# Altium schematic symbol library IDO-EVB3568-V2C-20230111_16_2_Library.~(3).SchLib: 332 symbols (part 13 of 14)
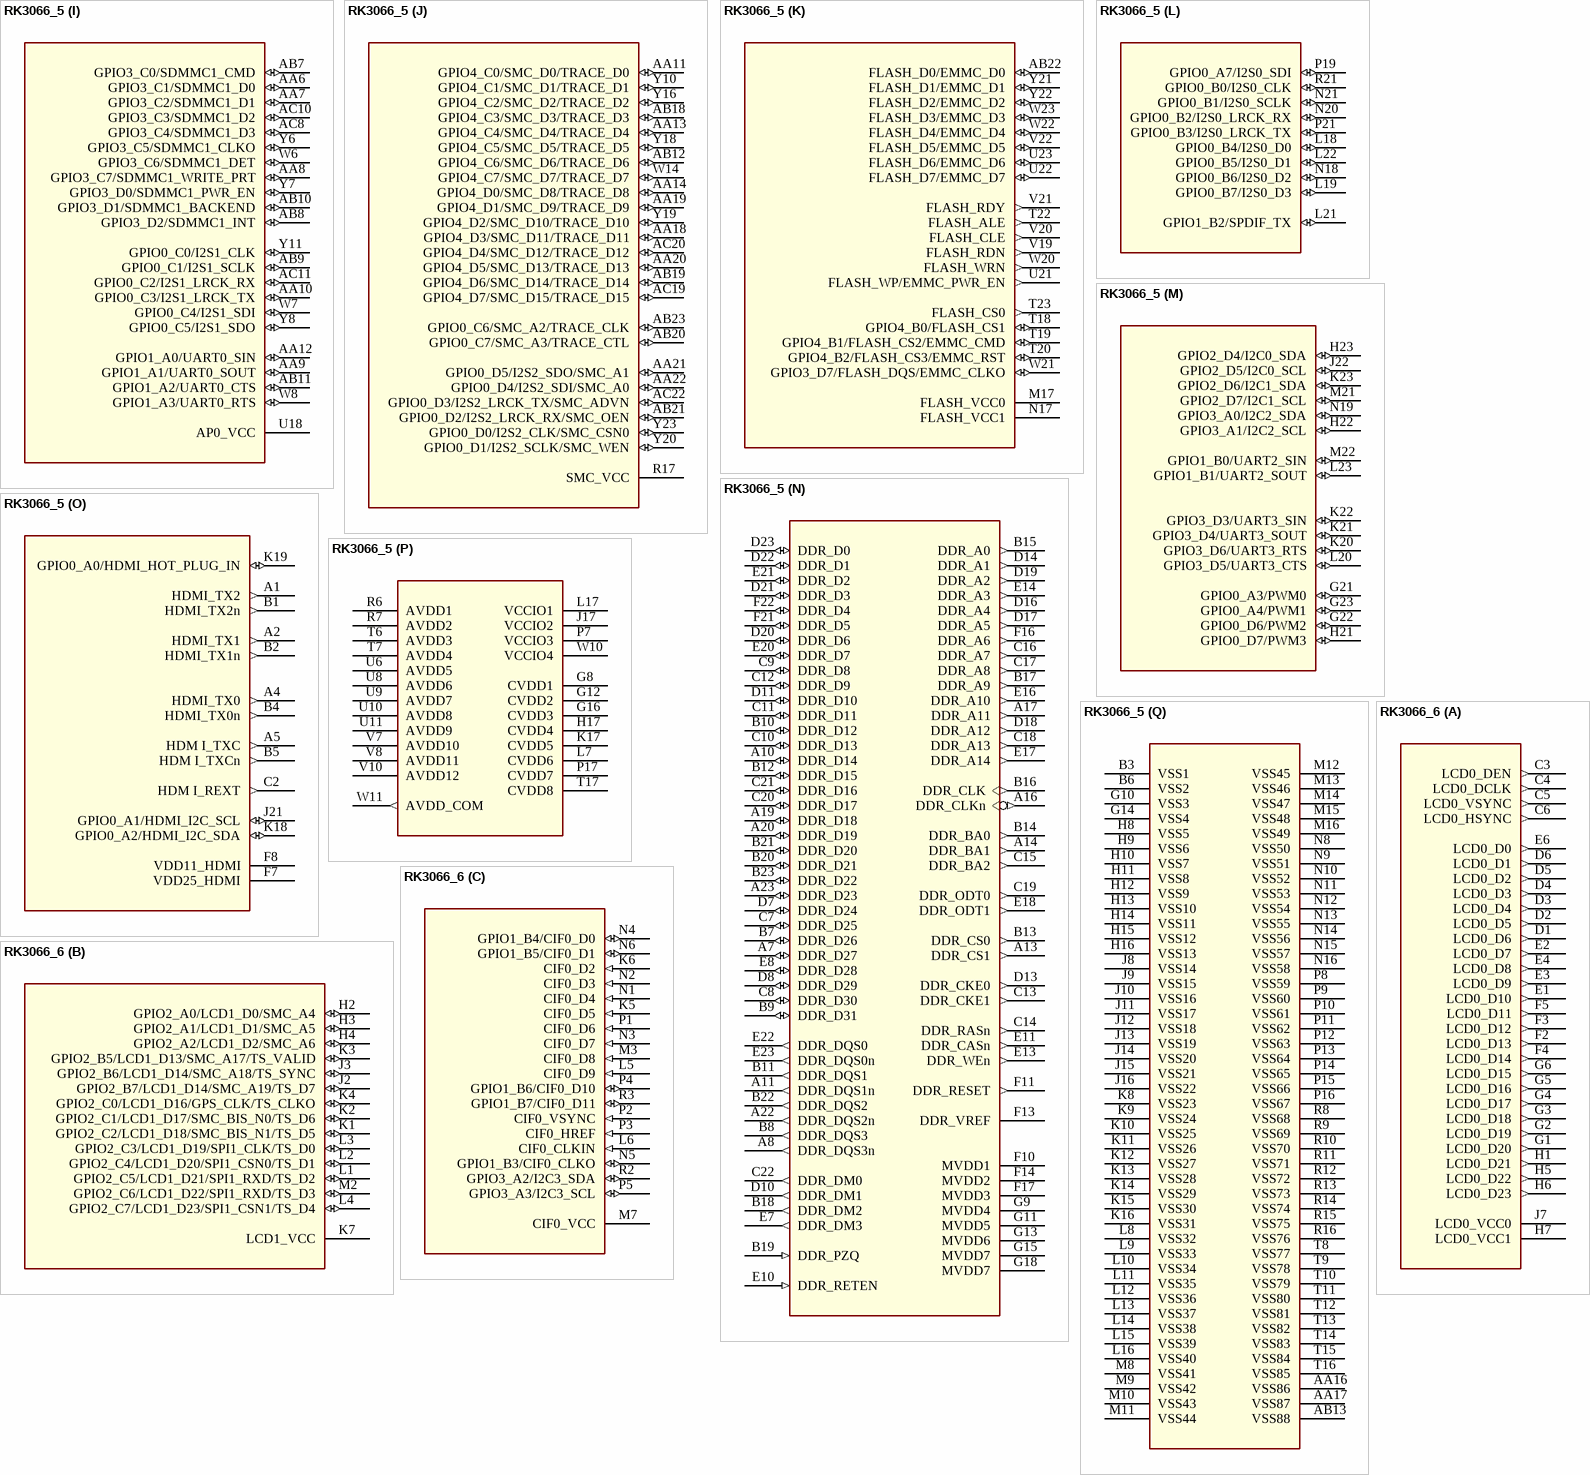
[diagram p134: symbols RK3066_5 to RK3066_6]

## RK3066_5
designator U?
Altium-Right: 230; Altium-Bottom: 180; Altium-Right1: 160; Altium-Bottom1: 120; Altium-Bottom2: 130; Altium-Bottom3: 280; Altium-Bottom4: 310; Altium-Bottom5: 270; Altium-Bottom6: 140; Altium-Bottom8: 530; Altium-Right9: 150; Altium-Bottom9: 250; Altium-Right10: 110; Altium-Bottom10: 170; Altium-Right11: 100; Altium-Bottom11: 470; Altium-Right12: 80; Altium-Bottom12: 350; Altium-Right13: 200; Altium-Bottom13: 190
footprint BGA453
part A pins: C3 LCD0_DEN (out), C4 LCD0_DCLK (out), C5 LCD0_VSYNC (out), C6 LCD0_HSYNC (out), D1 LCD0_D6 (out), D2 LCD0_D5 (out), D3 LCD0_D4 (out), D4 LCD0_D3 (out), D5 LCD0_D2 (out), D6 LCD0_D1 (out), E1 LCD0_D10 (out), E2 LCD0_D7 (out), E3 LCD0_D9 (out), E4 LCD0_D8 (out), E6 LCD0_D0 (out), F2 LCD0_D13 (out), F3 LCD0_D12 (out), F4 LCD0_D14 (out), F5 LCD0_D11 (out), G1 LCD0_D20 (out), G2 LCD0_D19 (out), G3 LCD0_D18 (out), G4 LCD0_D17 (out), G5 LCD0_D16 (out), G6 LCD0_D15 (out), H1 LCD0_D21 (out), H5 LCD0_D22 (out), H6 LCD0_D23 (out), H7 LCD0_VCC1 (power), J7 LCD0_VCC0 (power)
part B pins: H2 GPIO2_A0/LCD1_D0/SMC_A4 (io), H3 GPIO2_A1/LCD1_D1/SMC_A5 (io), H4 GPIO2_A2/LCD1_D2/SMC_A6 (io), J2 GPIO2_B7/LCD1_D14/SMC_A19/TS_D7 (io), J3 GPIO2_B6/LCD1_D14/SMC_A18/TS_SYNC (io), K1 GPIO2_C2/LCD1_D18/SMC_BIS_N1/TS_D5 (io), K2 GPIO2_C1/LCD1_D17/SMC_BIS_N0/TS_D6 (io), K3 GPIO2_B5/LCD1_D13/SMC_A17/TS_VALID (io), K4 GPIO2_C0/LCD1_D16/GPS_CLK/TS_CLKO (io), K7 LCD1_VCC (power), L1 GPIO2_C5/LCD1_D21/SPI1_RXD/TS_D2 (io), L2 GPIO2_C4/LCD1_D20/SPI1_CSN0/TS_D1 (io), L3 GPIO2_C3/LCD1_D19/SPI1_CLK/TS_D0 (io), L4 GPIO2_C7/LCD1_D23/SPI1_CSN1/TS_D4 (io), M2 GPIO2_C6/LCD1_D22/SPI1_RXD/TS_D3 (io)
part C pins: K5 CIF0_D5 (in), K6 CIF0_D2 (in), L5 CIF0_D9 (in), L6 CIF0_CLKIN (in), M3 CIF0_D8 (in), M7 CIF0_VCC (power), N1 CIF0_D4 (in), N2 CIF0_D3 (in), N3 CIF0_D7 (in), N4 GPIO1_B4/CIF0_D0 (io), N5 GPIO1_B3/CIF0_CLKO (io), N6 GPIO1_B5/CIF0_D1 (io), P1 CIF0_D6 (in), P2 CIF0_VSYNC (in), P3 CIF0_HREF (in), P4 GPIO1_B6/CIF0_D10 (io), P5 GPIO3_A3/I2C3_SCL (io), R2 GPIO3_A2/I2C3_SDA (io), R3 GPIO1_B7/CIF0_D11 (io)
part D pins: N7 CIF1_VCC (power), T1 GPIO1_C5/CIF1_D7/RMII_CRS_DVALID (io), T2 GPIO1_C0/CIF1_D2/RMII_CLKO (io), T3 GPIO1_C2/CIF1_D4/RMII_TXD1 (io), T4 GPIO1_C1/CIF1_D3/RMII_TX_EN (io), T5 GPIO1_C7/CIF1_D9/RMII_RXD0 (io), U1 GPIO1_D2/CIF1_CLKIN (io), U2 GPIO1_C4/CIF1_D6/RMII_RX_ERR (io), U3 GPIO1_C3/CIF1_D5/RMII_TXD0 (io), U4 GPIO1_D0/CIF1_VSYNC/MII_MD (io), U5 GPIO3_A5/I2C4_SCL (io), V2 GPIO1_D7/CIF1_CLKO (io), V3 GPIO1_C6/CIF1_D8/RMII_RXD1 (io), V4 GPIO1_D1/CIF1_HREF/MII_MDCLK (io), V5 GPIO3_A4/I2C4_SDA (io), W4 GPIO1_D6/CIF1_D11 (io)
part E pins: AA2 GPIO6_A4 (io), AA3 GPIO6_A5 (io), AA15 PVCC_3V3 (power), AB1 GPIO6_B0 (io), AB2 GPIO6_B1 (io), AB3 GPIO6_A1 (io), AB4 GPIO6_A7 (io), AB14 XOUT24M (out), AC1 GPIO6_A0 (io), AC2 GPIO6_A3 (io), AC4 GPIO6_A2 (io), AC5 GPIO6_A6 (io), AC13 DDRIO_RET_EN (out), AC14 XIN24M (in), U12 AVSS_APLL (power), U13 AVSS_DPLL (power), U14 AVSS_C/GPLL (power), V11 APLL_1V1 (power), V13 DPLL_1V1 (power), V14 C/GPLL_1V1 (power), V17 EFUSE (in), W13 PVDD_1V1 (power), Y1 CPU_PWROFF (out), Y2 CORE_PWROFF (out), Y3 DDRIO_PWROFF (out), Y4 GPIO6_B2 (io), Y5 GPIO6_B3 (io), Y13 CLKIN_32K (in), Y14 NPOR (in)
part F pins: AB15 HOST_RKELVIN (out), AB16 OTG_DM (io), AB17 HOST_DM (io), AC16 OTG_DP (io), AC17 HOST_DP (io), F19 GPIO0_A6/HOST_DRV (io), F20 TDO (out), G19 TDI/CPR_BYPASS (in), G20 TRSTN (in), H18 TCK/HSSCAN_SHIFT_CLOCK (in), H19 TMS/PLL_BYPASS (io), H20 RECOVER (in), P20 GPIO0_A5/OTG_DRV (io), U15 USBVDD_1V1 (power), U16 USBVDD_2V5 (power), V16 USBVDD_3V3 (power), W1 SARADC_ANI0 (in), W2 SARADC_ANI2 (in), W3 SARADC_ANI1 (in), W16 OTG_RKELVIN (out), W17 OTG_VBUS (in), Y17 OTG_ID (in)
part G pins: AA4 GPIO1_A4/UART1_RX/SPI0_CSN0 (io), AA5 GPIO4_B7/SPI0_CSN1 (io), AB5 GPIO1_A5/UART1_TX/SPI0_CLK (io), AB6 GPIO1_A6/UART1_CTSN/SPI0_RXD (io), AC7 GPIO1_A7/UART1_RTSN/SPI0_TXD (io), W18 AP1_VCC (power)
part H pins: AC23 GPIO3_B6/SDMMC0_DET (io), N22 GPIO3_B4/SDMMC0_D2 (io), N23 GPIO3_B5/SDMMC0_D3 (io), P18 GPIO3_A6/SDMMC0_RSTNO (io), P22 GPIO3_B3/SDMMC0_D1 (io), P23 GPIO3_B7/SDMMC0_WRITE_PRT (io), R22 GPIO3_A7/SDMMC0_PWR_EN (io), T21 GPIO3_B0/SDMMC0_CLKOUT (io), U19 GPIO3_B2/SDMMC0_D0 (io), U20 GPIO3_B1/SDMMC0_CMD (io)
part I pins: AA6 GPIO3_C1/SDMMC1_D0 (io), AA7 GPIO3_C2/SDMMC1_D1 (io), AA8 GPIO3_C7/SDMMC1_WRITE_PRT (io), AA9 GPIO1_A1/UART0_SOUT (io), AA10 GPIO0_C3/I2S1_LRCK_TX (io), AA12 GPIO1_A0/UART0_SIN (io), AB7 GPIO3_C0/SDMMC1_CMD (io), AB8 GPIO3_D2/SDMMC1_INT (io), AB9 GPIO0_C1/I2S1_SCLK (io), AB10 GPIO3_D1/SDMMC1_BACKEND (io), AB11 GPIO1_A2/UART0_CTS (io), AC8 GPIO3_C4/SDMMC1_D3 (io), AC10 GPIO3_C3/SDMMC1_D2 (io), AC11 GPIO0_C2/I2S1_LRCK_RX (io), U18 AP0_VCC (power), W6 GPIO3_C6/SDMMC1_DET (io), W7 GPIO0_C4/I2S1_SDI (io), W8 GPIO1_A3/UART0_RTS (io), Y6 GPIO3_C5/SDMMC1_CLKO (io), Y7 GPIO3_D0/SDMMC1_PWR_EN (io), Y8 GPIO0_C5/I2S1_SDO (io), Y11 GPIO0_C0/I2S1_CLK (io)
part J pins: AA11 GPIO4_C0/SMC_D0/TRACE_D0 (io), AA13 GPIO4_C4/SMC_D4/TRACE_D4 (io), AA14 GPIO4_D0/SMC_D8/TRACE_D8 (io), AA18 GPIO4_D3/SMC_D11/TRACE_D11 (io), AA19 GPIO4_D1/SMC_D9/TRACE_D9 (io), AA20 GPIO4_D5/SMC_D13/TRACE_D13 (io), AA21 GPIO0_D5/I2S2_SDO/SMC_A1 (io), AA22 GPIO0_D4/I2S2_SDI/SMC_A0 (io), AB12 GPIO4_C6/SMC_D6/TRACE_D6 (io), AB18 GPIO4_C3/SMC_D3/TRACE_D3 (io), AB19 GPIO4_D6/SMC_D14/TRACE_D14 (io), AB20 GPIO0_C7/SMC_A3/TRACE_CTL (io), AB21 GPIO0_D2/I2S2_LRCK_RX/SMC_OEN (io), AB23 GPIO0_C6/SMC_A2/TRACE_CLK (io), AC19 GPIO4_D7/SMC_D15/TRACE_D15 (io), AC20 GPIO4_D4/SMC_D12/TRACE_D12 (io), AC22 GPIO0_D3/I2S2_LRCK_TX/SMC_ADVN (io), R17 SMC_VCC (power), W14 GPIO4_C7/SMC_D7/TRACE_D7 (io), Y10 GPIO4_C1/SMC_D1/TRACE_D1 (io), Y16 GPIO4_C2/SMC_D2/TRACE_D2 (io), Y18 GPIO4_C5/SMC_D5/TRACE_D5 (io), Y19 GPIO4_D2/SMC_D10/TRACE_D10 (io), Y20 GPIO0_D1/I2S2_SCLK/SMC_WEN (io), Y23 GPIO0_D0/I2S2_CLK/SMC_CSN0 (io)
part K pins: AB22 FLASH_D0/EMMC_D0 (io), M17 FLASH_VCC0 (power), N17 FLASH_VCC1 (power), T18 GPIO4_B0/FLASH_CS1 (io), T19 GPIO4_B1/FLASH_CS2/EMMC_CMD (io), T20 GPIO4_B2/FLASH_CS3/EMMC_RST (io), T22 FLASH_ALE (out), T23 FLASH_CS0 (out), U21 FLASH_WP/EMMC_PWR_EN (out), U22 FLASH_D7/EMMC_D7 (io), U23 FLASH_D6/EMMC_D6 (io), V19 FLASH_RDN (out), V20 FLASH_CLE (out), V21 FLASH_RDY (out), V22 FLASH_D5/EMMC_D5 (io), W20 FLASH_WRN (out), W21 GPIO3_D7/FLASH_DQS/EMMC_CLKO (io), W22 FLASH_D4/EMMC_D4 (io), W23 FLASH_D3/EMMC_D3 (io), Y21 FLASH_D1/EMMC_D1 (io), Y22 FLASH_D2/EMMC_D2 (io)
part L pins: L18 GPIO0_B4/I2S0_D0 (io), L19 GPIO0_B7/I2S0_D3 (io), L21 GPIO1_B2/SPDIF_TX (io), L22 GPIO0_B5/I2S0_D1 (io), N18 GPIO0_B6/I2S0_D2 (io), N20 GPIO0_B2/I2S0_LRCK_RX (io), N21 GPIO0_B1/I2S0_SCLK (io), P19 GPIO0_A7/I2S0_SDI (io), P21 GPIO0_B3/I2S0_LRCK_TX (io), R21 GPIO0_B0/I2S0_CLK (io)
part M pins: G21 GPIO0_A3/PWM0 (io), G22 GPIO0_D6/PWM2 (io), G23 GPIO0_A4/PWM1 (io), H21 GPIO0_D7/PWM3 (io), H22 GPIO3_A1/I2C2_SCL (io), H23 GPIO2_D4/I2C0_SDA (io), J22 GPIO2_D5/I2C0_SCL (io), K20 GPIO3_D6/UART3_RTS (io), K21 GPIO3_D4/UART3_SOUT (io), K22 GPIO3_D3/UART3_SIN (io), K23 GPIO2_D6/I2C1_SDA (io), L20 GPIO3_D5/UART3_CTS (io), L23 GPIO1_B1/UART2_SOUT (io), M21 GPIO2_D7/I2C1_SCL (io), M22 GPIO1_B0/UART2_SIN (io), N19 GPIO3_A0/I2C2_SDA (io)
part N pins: A7 DDR_D27 (io), A8 DDR_DQS3n (out), A10 DDR_D14 (io), A11 DDR_DQS1n (out), A13 DDR_CS1 (out), A14 DDR_BA1 (out), A16 DDR_CLKn (out), A17 DDR_A11 (out), A19 DDR_D18 (io), A20 DDR_D19 (io), A22 DDR_DQS2n (out), A23 DDR_D23 (io), B7 DDR_D26 (io), B8 DDR_DQS3 (out), B9 DDR_D31 (io), B10 DDR_D12 (io), B11 DDR_DQS1 (out), B12 DDR_D15 (io), B13 DDR_CS0 (out), B14 DDR_BA0 (out), B15 DDR_A0 (out), B16 DDR_CLK (out), B17 DDR_A9 (out), B18 DDR_DM2 (out), B19 DDR_PZQ (in), B20 DDR_D21 (io), B21 DDR_D20 (io), B22 DDR_DQS2 (out), B23 DDR_D22 (io), C7 DDR_D25 (io), C8 DDR_D30 (io), C9 DDR_D8 (io), C10 DDR_D13 (io), C11 DDR_D11 (io), C12 DDR_D9 (io), C13 DDR_CKE1 (out), C14 DDR_RASn (out), C15 DDR_BA2 (out), C16 DDR_A7 (out), C17 DDR_A8 (out), C18 DDR_A13 (out), C19 DDR_ODT0 (out), C20 DDR_D17 (io), C21 DDR_D16 (io), C22 DDR_DM0 (out), D7 DDR_D24 (io), D8 DDR_D29 (io), D10 DDR_DM1 (out), D11 DDR_D10 (io), D13 DDR_CKE0 (out), D14 DDR_A1 (out), D16 DDR_A4 (out), D17 DDR_A5 (out), D18 DDR_A12 (out), D19 DDR_A2 (out), D20 DDR_D6 (io), D21 DDR_D3 (io), D22 DDR_D1 (io), D23 DDR_D0 (io), E7 DDR_DM3 (out), E8 DDR_D28 (io), E10 DDR_RETEN (in), E11 DDR_CASn (out), E13 DDR_WEn (out), E14 DDR_A3 (out), E16 DDR_A10 (out), E17 DDR_A14 (out), E18 DDR_ODT1 (out), E20 DDR_D7 (io), E21 DDR_D2 (io), E22 DDR_DQS0 (out), E23 DDR_DQS0n (out), F10 MVDD1 (power), F11 DDR_RESET (out), F13 DDR_VREF (power), F14 MVDD2 (power), F16 DDR_A6 (out), F17 MVDD3 (power), F21 DDR_D5 (io), F22 DDR_D4 (io), G9 MVDD4 (power), G11 MVDD5 (power), G13 MVDD6 (power), G15 MVDD7 (power), G18 MVDD7 (power)
part O pins: A1 HDMI_TX2 (out), A2 HDMI_TX1 (out), A4 HDMI_TX0 (out), A5 HDM I_TXC (out), B1 HDMI_TX2n (out), B2 HDMI_TX1n (out), B4 HDMI_TX0n (out), B5 HDM I_TXCn (out), C2 HDM I_REXT (out), F7 VDD25_HDMI (power), F8 VDD11_HDMI (power), J21 GPIO0_A1/HDMI_I2C_SCL (io), K18 GPIO0_A2/HDMI_I2C_SDA (io), K19 GPIO0_A0/HDMI_HOT_PLUG_IN (io)
part P pins: G8 CVDD1 (power), G12 CVDD2 (power), G16 CVDD3 (power), H17 CVDD4 (power), J17 VCCIO2 (power), K17 CVDD5 (power), L7 CVDD6 (power), L17 VCCIO1 (power), P7 VCCIO3 (power), P17 CVDD7 (power), R6 AVDD1 (power), R7 AVDD2 (power), T6 AVDD3 (power), T7 AVDD4 (power), T17 CVDD8 (power), U6 AVDD5 (power), U8 AVDD6 (power), U9 AVDD7 (power), U10 AVDD8 (power), U11 AVDD9 (power), V7 AVDD10 (power), V8 AVDD11 (power), V10 AVDD12 (power), W10 VCCIO4 (power), W11 AVDD_COM (out)
part Q pins: AA16 VSS86 (power), AA17 VSS87 (power), AB13 VSS88 (power), B3 VSS1 (power), B6 VSS2 (power), G10 VSS3 (power), G14 VSS4 (power), H8 VSS5 (power), H9 VSS6 (power), H10 VSS7 (power), H11 VSS8 (power), H12 VSS9 (power), H13 VSS10 (power), H14 VSS11 (power), H15 VSS12 (power), H16 VSS13 (power), J8 VSS14 (power), J9 VSS15 (power), J10 VSS16 (power), J11 VSS17 (power), J12 VSS18 (power), J13 VSS19 (power), J14 VSS20 (power), J15 VSS21 (power), J16 VSS22 (power), K8 VSS23 (power), K9 VSS24 (power), K10 VSS25 (power), K11 VSS26 (power), K12 VSS27 (power), K13 VSS28 (power), K14 VSS29 (power), K15 VSS30 (power), K16 VSS31 (power), L8 VSS32 (power), L9 VSS33 (power), L10 VSS34 (power), L11 VSS35 (power), L12 VSS36 (power), L13 VSS37 (power), L14 VSS38 (power), L15 VSS39 (power), L16 VSS40 (power), M8 VSS41 (power), M9 VSS42 (power), M10 VSS43 (power), M11 VSS44 (power), M12 VSS45 (power), M13 VSS46 (power), M14 VSS47 (power), M15 VSS48 (power), M16 VSS49 (power), N8 VSS50 (power), N9 VSS51 (power), N10 VSS52 (power), N11 VSS53 (power), N12 VSS54 (power), N13 VSS55 (power), N14 VSS56 (power), N15 VSS57 (power), N16 VSS58 (power), P8 VSS59 (power), P9 VSS60 (power), P10 VSS61 (power), P11 VSS62 (power), P12 VSS63 (power), P13 VSS64 (power), P14 VSS65 (power), P15 VSS66 (power), P16 VSS67 (power), R8 VSS68 (power), R9 VSS69 (power), R10 VSS70 (power), R11 VSS71 (power), R12 VSS72 (power), R13 VSS73 (power), R14 VSS74 (power), R15 VSS75 (power), R16 VSS76 (power), T8 VSS77 (power), T9 VSS78 (power), T10 VSS79 (power), T11 VSS80 (power), T12 VSS81 (power), T13 VSS82 (power), T14 VSS83 (power), T15 VSS84 (power), T16 VSS85 (power)

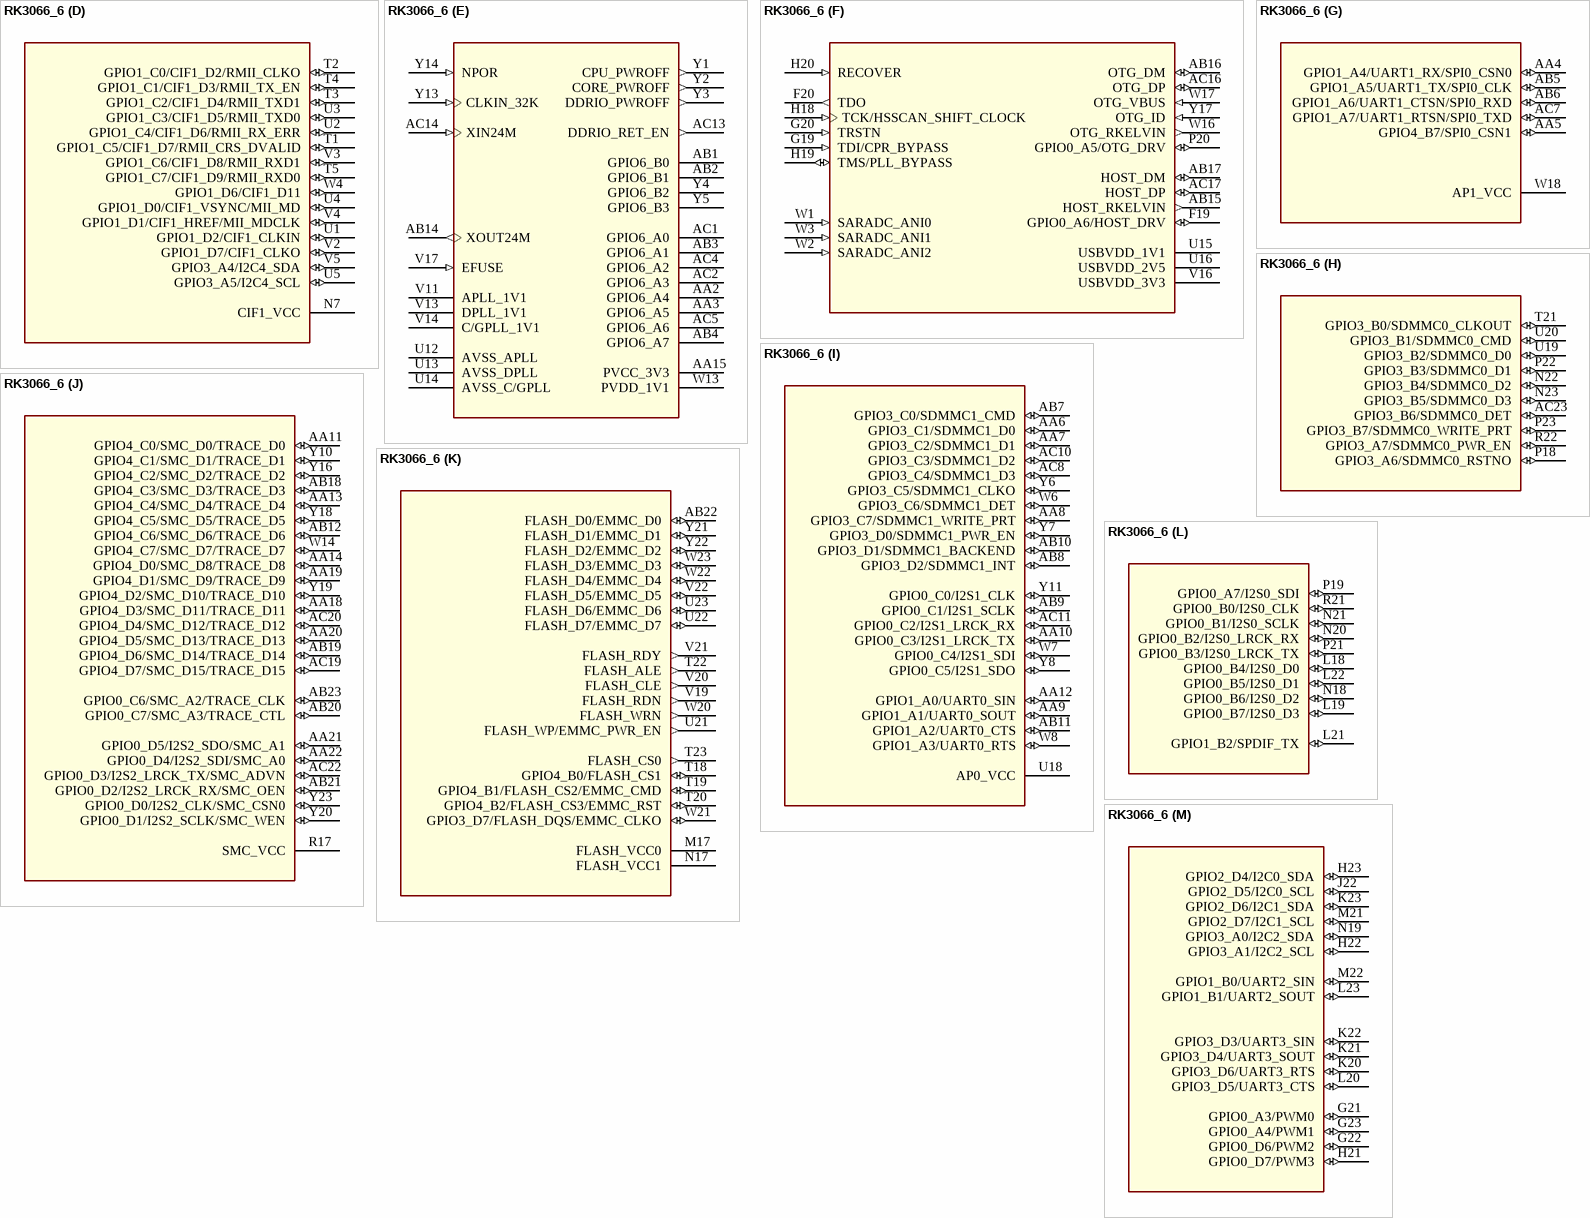
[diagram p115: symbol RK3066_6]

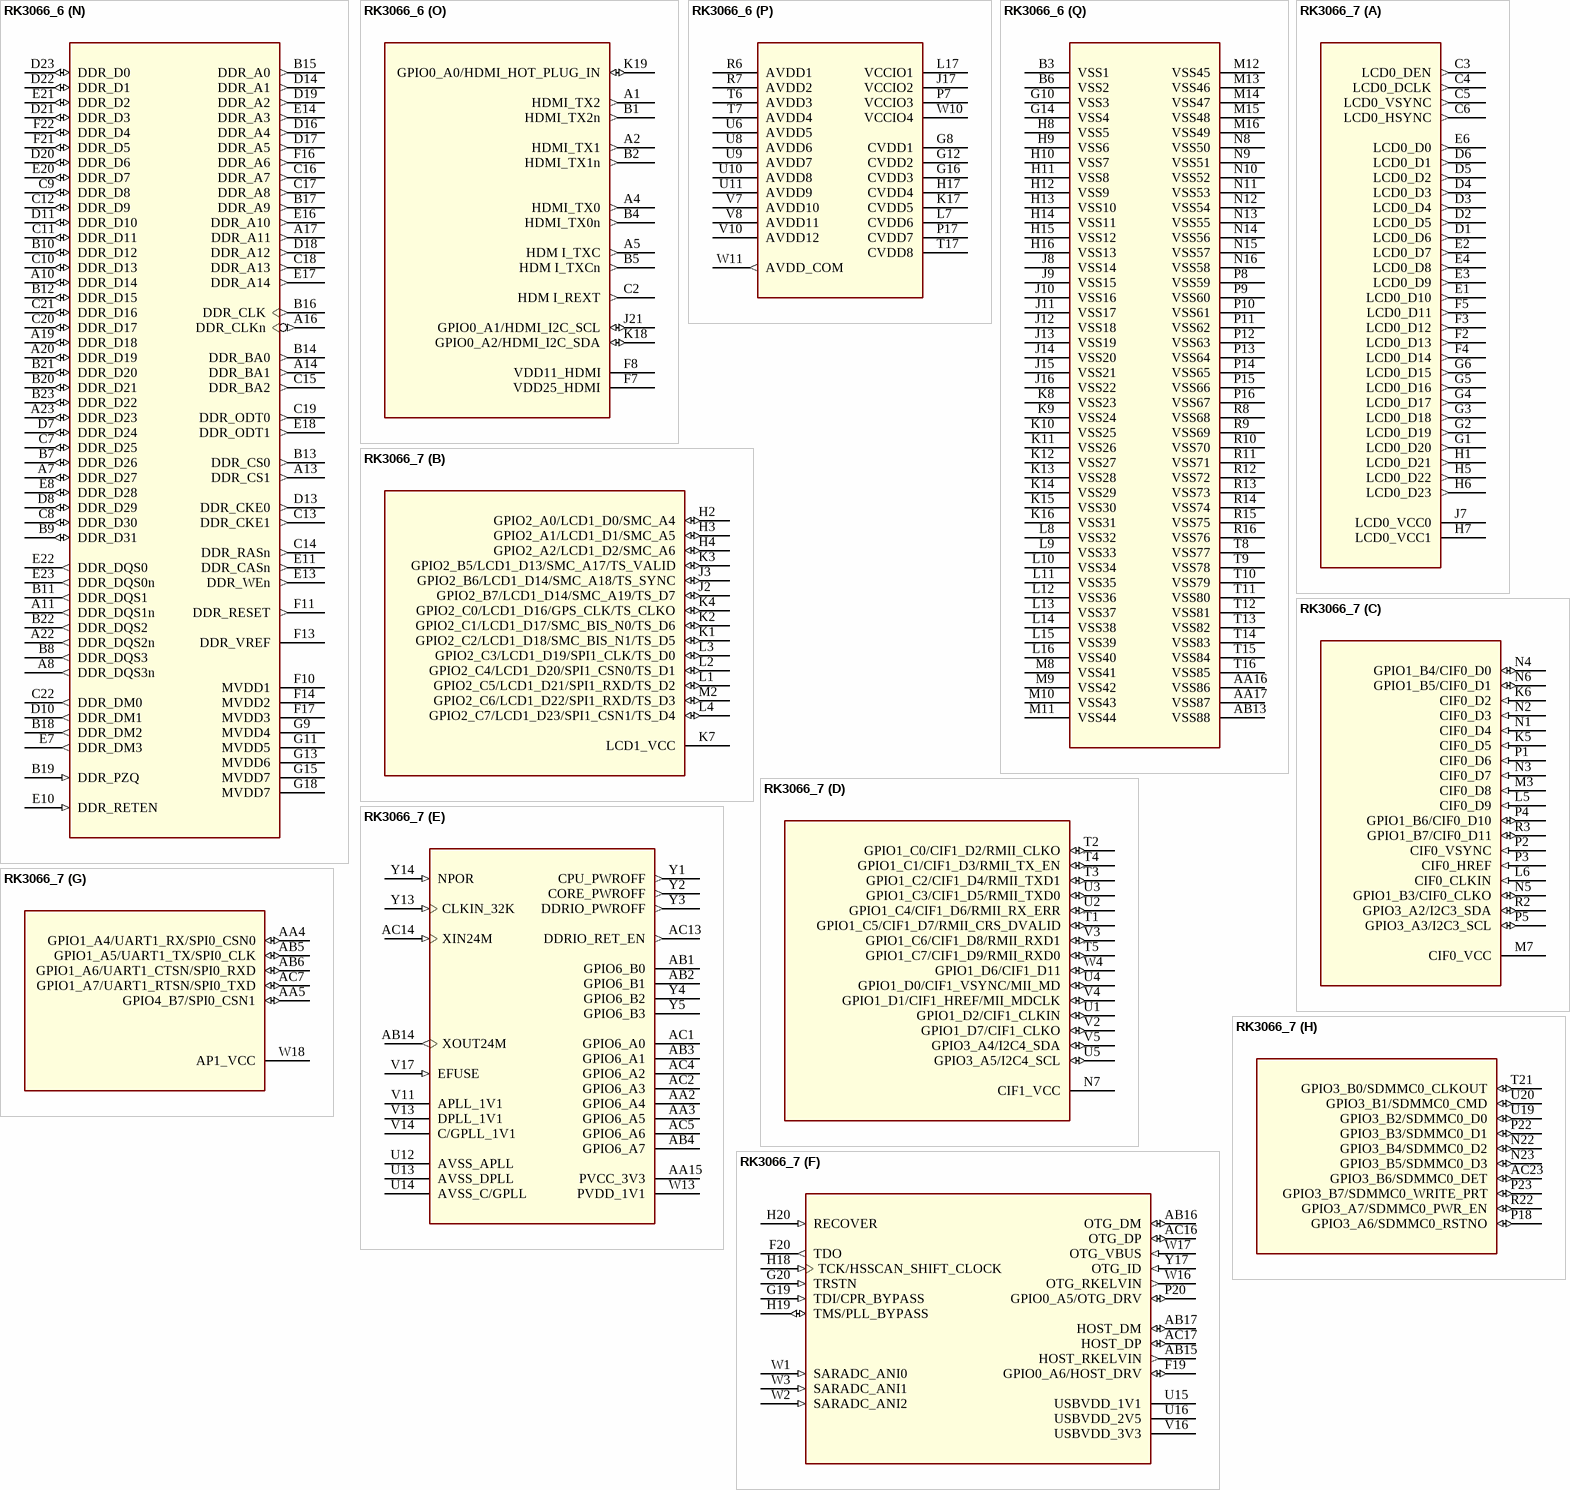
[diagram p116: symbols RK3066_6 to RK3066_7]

## RK3066_6
designator U?
Altium-Right: 160; Altium-Bottom: 120; Altium-Bottom1: 130; Altium-Bottom2: 280; Altium-Right3: 180; Altium-Bottom3: 310; Altium-Bottom4: 270; Altium-Bottom5: 140; Altium-Bottom6: 230; Altium-Bottom7: 530; Altium-Right8: 150; Altium-Bottom8: 250; Altium-Right9: 110; Altium-Bottom9: 170; Altium-Right10: 100; Altium-Bottom10: 470; Altium-Right11: 80; Altium-Bottom11: 350; Altium-Right12: 200; Altium-Bottom12: 190
footprint BGA453
part A pins: C3 LCD0_DEN (out), C4 LCD0_DCLK (out), C5 LCD0_VSYNC (out), C6 LCD0_HSYNC (out), D1 LCD0_D6 (out), D2 LCD0_D5 (out), D3 LCD0_D4 (out), D4 LCD0_D3 (out), D5 LCD0_D2 (out), D6 LCD0_D1 (out), E1 LCD0_D10 (out), E2 LCD0_D7 (out), E3 LCD0_D9 (out), E4 LCD0_D8 (out), E6 LCD0_D0 (out), F2 LCD0_D13 (out), F3 LCD0_D12 (out), F4 LCD0_D14 (out), F5 LCD0_D11 (out), G1 LCD0_D20 (out), G2 LCD0_D19 (out), G3 LCD0_D18 (out), G4 LCD0_D17 (out), G5 LCD0_D16 (out), G6 LCD0_D15 (out), H1 LCD0_D21 (out), H5 LCD0_D22 (out), H6 LCD0_D23 (out), H7 LCD0_VCC1 (power), J7 LCD0_VCC0 (power)
part B pins: H2 GPIO2_A0/LCD1_D0/SMC_A4 (io), H3 GPIO2_A1/LCD1_D1/SMC_A5 (io), H4 GPIO2_A2/LCD1_D2/SMC_A6 (io), J2 GPIO2_B7/LCD1_D14/SMC_A19/TS_D7 (io), J3 GPIO2_B6/LCD1_D14/SMC_A18/TS_SYNC (io), K1 GPIO2_C2/LCD1_D18/SMC_BIS_N1/TS_D5 (io), K2 GPIO2_C1/LCD1_D17/SMC_BIS_N0/TS_D6 (io), K3 GPIO2_B5/LCD1_D13/SMC_A17/TS_VALID (io), K4 GPIO2_C0/LCD1_D16/GPS_CLK/TS_CLKO (io), K7 LCD1_VCC (power), L1 GPIO2_C5/LCD1_D21/SPI1_RXD/TS_D2 (io), L2 GPIO2_C4/LCD1_D20/SPI1_CSN0/TS_D1 (io), L3 GPIO2_C3/LCD1_D19/SPI1_CLK/TS_D0 (io), L4 GPIO2_C7/LCD1_D23/SPI1_CSN1/TS_D4 (io), M2 GPIO2_C6/LCD1_D22/SPI1_RXD/TS_D3 (io)
part C pins: K5 CIF0_D5 (in), K6 CIF0_D2 (in), L5 CIF0_D9 (in), L6 CIF0_CLKIN (in), M3 CIF0_D8 (in), M7 CIF0_VCC (power), N1 CIF0_D4 (in), N2 CIF0_D3 (in), N3 CIF0_D7 (in), N4 GPIO1_B4/CIF0_D0 (io), N5 GPIO1_B3/CIF0_CLKO (io), N6 GPIO1_B5/CIF0_D1 (io), P1 CIF0_D6 (in), P2 CIF0_VSYNC (in), P3 CIF0_HREF (in), P4 GPIO1_B6/CIF0_D10 (io), P5 GPIO3_A3/I2C3_SCL (io), R2 GPIO3_A2/I2C3_SDA (io), R3 GPIO1_B7/CIF0_D11 (io)
part D pins: N7 CIF1_VCC (power), T1 GPIO1_C5/CIF1_D7/RMII_CRS_DVALID (io), T2 GPIO1_C0/CIF1_D2/RMII_CLKO (io), T3 GPIO1_C2/CIF1_D4/RMII_TXD1 (io), T4 GPIO1_C1/CIF1_D3/RMII_TX_EN (io), T5 GPIO1_C7/CIF1_D9/RMII_RXD0 (io), U1 GPIO1_D2/CIF1_CLKIN (io), U2 GPIO1_C4/CIF1_D6/RMII_RX_ERR (io), U3 GPIO1_C3/CIF1_D5/RMII_TXD0 (io), U4 GPIO1_D0/CIF1_VSYNC/MII_MD (io), U5 GPIO3_A5/I2C4_SCL (io), V2 GPIO1_D7/CIF1_CLKO (io), V3 GPIO1_C6/CIF1_D8/RMII_RXD1 (io), V4 GPIO1_D1/CIF1_HREF/MII_MDCLK (io), V5 GPIO3_A4/I2C4_SDA (io), W4 GPIO1_D6/CIF1_D11 (io)
part E pins: AA2 GPIO6_A4, AA3 GPIO6_A5, AA15 PVCC_3V3 (power), AB1 GPIO6_B0, AB2 GPIO6_B1, AB3 GPIO6_A1, AB4 GPIO6_A7, AB14 XOUT24M (out), AC1 GPIO6_A0, AC2 GPIO6_A3, AC4 GPIO6_A2, AC5 GPIO6_A6, AC13 DDRIO_RET_EN (out), AC14 XIN24M (in), U12 AVSS_APLL (power), U13 AVSS_DPLL (power), U14 AVSS_C/GPLL (power), V11 APLL_1V1 (power), V13 DPLL_1V1 (power), V14 C/GPLL_1V1 (power), V17 EFUSE (in), W13 PVDD_1V1 (power), Y1 CPU_PWROFF (out), Y2 CORE_PWROFF (out), Y3 DDRIO_PWROFF (out), Y4 GPIO6_B2, Y5 GPIO6_B3, Y13 CLKIN_32K (in), Y14 NPOR (in)
part F pins: AB15 HOST_RKELVIN (out), AB16 OTG_DM (io), AB17 HOST_DM (io), AC16 OTG_DP (io), AC17 HOST_DP (io), F19 GPIO0_A6/HOST_DRV (io), F20 TDO (out), G19 TDI/CPR_BYPASS (in), G20 TRSTN (in), H18 TCK/HSSCAN_SHIFT_CLOCK (in), H19 TMS/PLL_BYPASS (io), H20 RECOVER (in), P20 GPIO0_A5/OTG_DRV (io), U15 USBVDD_1V1 (power), U16 USBVDD_2V5 (power), V16 USBVDD_3V3 (power), W1 SARADC_ANI0 (in), W2 SARADC_ANI2 (in), W3 SARADC_ANI1 (in), W16 OTG_RKELVIN (out), W17 OTG_VBUS (in), Y17 OTG_ID (in)
part G pins: AA4 GPIO1_A4/UART1_RX/SPI0_CSN0 (io), AA5 GPIO4_B7/SPI0_CSN1 (io), AB5 GPIO1_A5/UART1_TX/SPI0_CLK (io), AB6 GPIO1_A6/UART1_CTSN/SPI0_RXD (io), AC7 GPIO1_A7/UART1_RTSN/SPI0_TXD (io), W18 AP1_VCC (power)
part H pins: AC23 GPIO3_B6/SDMMC0_DET (io), N22 GPIO3_B4/SDMMC0_D2 (io), N23 GPIO3_B5/SDMMC0_D3 (io), P18 GPIO3_A6/SDMMC0_RSTNO (io), P22 GPIO3_B3/SDMMC0_D1 (io), P23 GPIO3_B7/SDMMC0_WRITE_PRT (io), R22 GPIO3_A7/SDMMC0_PWR_EN (io), T21 GPIO3_B0/SDMMC0_CLKOUT (io), U19 GPIO3_B2/SDMMC0_D0 (io), U20 GPIO3_B1/SDMMC0_CMD (io)
part I pins: AA6 GPIO3_C1/SDMMC1_D0 (io), AA7 GPIO3_C2/SDMMC1_D1 (io), AA8 GPIO3_C7/SDMMC1_WRITE_PRT (io), AA9 GPIO1_A1/UART0_SOUT (io), AA10 GPIO0_C3/I2S1_LRCK_TX (io), AA12 GPIO1_A0/UART0_SIN (io), AB7 GPIO3_C0/SDMMC1_CMD (io), AB8 GPIO3_D2/SDMMC1_INT (io), AB9 GPIO0_C1/I2S1_SCLK (io), AB10 GPIO3_D1/SDMMC1_BACKEND (io), AB11 GPIO1_A2/UART0_CTS (io), AC8 GPIO3_C4/SDMMC1_D3 (io), AC10 GPIO3_C3/SDMMC1_D2 (io), AC11 GPIO0_C2/I2S1_LRCK_RX (io), U18 AP0_VCC (power), W6 GPIO3_C6/SDMMC1_DET (io), W7 GPIO0_C4/I2S1_SDI (io), W8 GPIO1_A3/UART0_RTS (io), Y6 GPIO3_C5/SDMMC1_CLKO (io), Y7 GPIO3_D0/SDMMC1_PWR_EN (io), Y8 GPIO0_C5/I2S1_SDO (io), Y11 GPIO0_C0/I2S1_CLK (io)
part J pins: AA11 GPIO4_C0/SMC_D0/TRACE_D0 (io), AA13 GPIO4_C4/SMC_D4/TRACE_D4 (io), AA14 GPIO4_D0/SMC_D8/TRACE_D8 (io), AA18 GPIO4_D3/SMC_D11/TRACE_D11 (io), AA19 GPIO4_D1/SMC_D9/TRACE_D9 (io), AA20 GPIO4_D5/SMC_D13/TRACE_D13 (io), AA21 GPIO0_D5/I2S2_SDO/SMC_A1 (io), AA22 GPIO0_D4/I2S2_SDI/SMC_A0 (io), AB12 GPIO4_C6/SMC_D6/TRACE_D6 (io), AB18 GPIO4_C3/SMC_D3/TRACE_D3 (io), AB19 GPIO4_D6/SMC_D14/TRACE_D14 (io), AB20 GPIO0_C7/SMC_A3/TRACE_CTL (io), AB21 GPIO0_D2/I2S2_LRCK_RX/SMC_OEN (io), AB23 GPIO0_C6/SMC_A2/TRACE_CLK (io), AC19 GPIO4_D7/SMC_D15/TRACE_D15 (io), AC20 GPIO4_D4/SMC_D12/TRACE_D12 (io), AC22 GPIO0_D3/I2S2_LRCK_TX/SMC_ADVN (io), R17 SMC_VCC (power), W14 GPIO4_C7/SMC_D7/TRACE_D7 (io), Y10 GPIO4_C1/SMC_D1/TRACE_D1 (io), Y16 GPIO4_C2/SMC_D2/TRACE_D2 (io), Y18 GPIO4_C5/SMC_D5/TRACE_D5 (io), Y19 GPIO4_D2/SMC_D10/TRACE_D10 (io), Y20 GPIO0_D1/I2S2_SCLK/SMC_WEN (io), Y23 GPIO0_D0/I2S2_CLK/SMC_CSN0 (io)
part K pins: AB22 FLASH_D0/EMMC_D0 (io), M17 FLASH_VCC0 (power), N17 FLASH_VCC1 (power), T18 GPIO4_B0/FLASH_CS1 (io), T19 GPIO4_B1/FLASH_CS2/EMMC_CMD (io), T20 GPIO4_B2/FLASH_CS3/EMMC_RST (io), T22 FLASH_ALE (out), T23 FLASH_CS0 (out), U21 FLASH_WP/EMMC_PWR_EN (out), U22 FLASH_D7/EMMC_D7 (io), U23 FLASH_D6/EMMC_D6 (io), V19 FLASH_RDN (out), V20 FLASH_CLE (out), V21 FLASH_RDY (out), V22 FLASH_D5/EMMC_D5 (io), W20 FLASH_WRN (out), W21 GPIO3_D7/FLASH_DQS/EMMC_CLKO (io), W22 FLASH_D4/EMMC_D4 (io), W23 FLASH_D3/EMMC_D3 (io), Y21 FLASH_D1/EMMC_D1 (io), Y22 FLASH_D2/EMMC_D2 (io)
part L pins: L18 GPIO0_B4/I2S0_D0 (io), L19 GPIO0_B7/I2S0_D3 (io), L21 GPIO1_B2/SPDIF_TX (io), L22 GPIO0_B5/I2S0_D1 (io), N18 GPIO0_B6/I2S0_D2 (io), N20 GPIO0_B2/I2S0_LRCK_RX (io), N21 GPIO0_B1/I2S0_SCLK (io), P19 GPIO0_A7/I2S0_SDI (io), P21 GPIO0_B3/I2S0_LRCK_TX (io), R21 GPIO0_B0/I2S0_CLK (io)
part M pins: G21 GPIO0_A3/PWM0 (io), G22 GPIO0_D6/PWM2 (io), G23 GPIO0_A4/PWM1 (io), H21 GPIO0_D7/PWM3 (io), H22 GPIO3_A1/I2C2_SCL (io), H23 GPIO2_D4/I2C0_SDA (io), J22 GPIO2_D5/I2C0_SCL (io), K20 GPIO3_D6/UART3_RTS (io), K21 GPIO3_D4/UART3_SOUT (io), K22 GPIO3_D3/UART3_SIN (io), K23 GPIO2_D6/I2C1_SDA (io), L20 GPIO3_D5/UART3_CTS (io), L23 GPIO1_B1/UART2_SOUT (io), M21 GPIO2_D7/I2C1_SCL (io), M22 GPIO1_B0/UART2_SIN (io), N19 GPIO3_A0/I2C2_SDA (io)
part N pins: A7 DDR_D27 (io), A8 DDR_DQS3n (out), A10 DDR_D14 (io), A11 DDR_DQS1n (out), A13 DDR_CS1 (out), A14 DDR_BA1 (out), A16 DDR_CLKn (out), A17 DDR_A11 (out), A19 DDR_D18 (io), A20 DDR_D19 (io), A22 DDR_DQS2n (out), A23 DDR_D23 (io), B7 DDR_D26 (io), B8 DDR_DQS3 (out), B9 DDR_D31 (io), B10 DDR_D12 (io), B11 DDR_DQS1 (out), B12 DDR_D15 (io), B13 DDR_CS0 (out), B14 DDR_BA0 (out), B15 DDR_A0 (out), B16 DDR_CLK (out), B17 DDR_A9 (out), B18 DDR_DM2 (out), B19 DDR_PZQ (in), B20 DDR_D21 (io), B21 DDR_D20 (io), B22 DDR_DQS2 (out), B23 DDR_D22 (io), C7 DDR_D25 (io), C8 DDR_D30 (io), C9 DDR_D8 (io), C10 DDR_D13 (io), C11 DDR_D11 (io), C12 DDR_D9 (io), C13 DDR_CKE1 (out), C14 DDR_RASn (out), C15 DDR_BA2 (out), C16 DDR_A7 (out), C17 DDR_A8 (out), C18 DDR_A13 (out), C19 DDR_ODT0 (out), C20 DDR_D17 (io), C21 DDR_D16 (io), C22 DDR_DM0 (out), D7 DDR_D24 (io), D8 DDR_D29 (io), D10 DDR_DM1 (out), D11 DDR_D10 (io), D13 DDR_CKE0 (out), D14 DDR_A1 (out), D16 DDR_A4 (out), D17 DDR_A5 (out), D18 DDR_A12 (out), D19 DDR_A2 (out), D20 DDR_D6 (io), D21 DDR_D3 (io), D22 DDR_D1 (io), D23 DDR_D0 (io), E7 DDR_DM3 (out), E8 DDR_D28 (io), E10 DDR_RETEN (in), E11 DDR_CASn (out), E13 DDR_WEn (out), E14 DDR_A3 (out), E16 DDR_A10 (out), E17 DDR_A14 (out), E18 DDR_ODT1 (out), E20 DDR_D7 (io), E21 DDR_D2 (io), E22 DDR_DQS0 (out), E23 DDR_DQS0n (out), F10 MVDD1 (power), F11 DDR_RESET (out), F13 DDR_VREF (power), F14 MVDD2 (power), F16 DDR_A6 (out), F17 MVDD3 (power), F21 DDR_D5 (io), F22 DDR_D4 (io), G9 MVDD4 (power), G11 MVDD5 (power), G13 MVDD6 (power), G15 MVDD7 (power), G18 MVDD7 (power)
part O pins: A1 HDMI_TX2 (out), A2 HDMI_TX1 (out), A4 HDMI_TX0 (out), A5 HDM I_TXC (out), B1 HDMI_TX2n (out), B2 HDMI_TX1n (out), B4 HDMI_TX0n (out), B5 HDM I_TXCn (out), C2 HDM I_REXT (out), F7 VDD25_HDMI (power), F8 VDD11_HDMI (power), J21 GPIO0_A1/HDMI_I2C_SCL (io), K18 GPIO0_A2/HDMI_I2C_SDA (io), K19 GPIO0_A0/HDMI_HOT_PLUG_IN (io)
part P pins: G8 CVDD1 (power), G12 CVDD2 (power), G16 CVDD3 (power), H17 CVDD4 (power), J17 VCCIO2 (power), K17 CVDD5 (power), L7 CVDD6 (power), L17 VCCIO1 (power), P7 VCCIO3 (power), P17 CVDD7 (power), R6 AVDD1 (power), R7 AVDD2 (power), T6 AVDD3 (power), T7 AVDD4 (power), T17 CVDD8 (power), U6 AVDD5 (power), U8 AVDD6 (power), U9 AVDD7 (power), U10 AVDD8 (power), U11 AVDD9 (power), V7 AVDD10 (power), V8 AVDD11 (power), V10 AVDD12 (power), W10 VCCIO4 (power), W11 AVDD_COM (out)
part Q pins: AA16 VSS86 (power), AA17 VSS87 (power), AB13 VSS88 (power), B3 VSS1 (power), B6 VSS2 (power), G10 VSS3 (power), G14 VSS4 (power), H8 VSS5 (power), H9 VSS6 (power), H10 VSS7 (power), H11 VSS8 (power), H12 VSS9 (power), H13 VSS10 (power), H14 VSS11 (power), H15 VSS12 (power), H16 VSS13 (power), J8 VSS14 (power), J9 VSS15 (power), J10 VSS16 (power), J11 VSS17 (power), J12 VSS18 (power), J13 VSS19 (power), J14 VSS20 (power), J15 VSS21 (power), J16 VSS22 (power), K8 VSS23 (power), K9 VSS24 (power), K10 VSS25 (power), K11 VSS26 (power), K12 VSS27 (power), K13 VSS28 (power), K14 VSS29 (power), K15 VSS30 (power), K16 VSS31 (power), L8 VSS32 (power), L9 VSS33 (power), L10 VSS34 (power), L11 VSS35 (power), L12 VSS36 (power), L13 VSS37 (power), L14 VSS38 (power), L15 VSS39 (power), L16 VSS40 (power), M8 VSS41 (power), M9 VSS42 (power), M10 VSS43 (power), M11 VSS44 (power), M12 VSS45 (power), M13 VSS46 (power), M14 VSS47 (power), M15 VSS48 (power), M16 VSS49 (power), N8 VSS50 (power), N9 VSS51 (power), N10 VSS52 (power), N11 VSS53 (power), N12 VSS54 (power), N13 VSS55 (power), N14 VSS56 (power), N15 VSS57 (power), N16 VSS58 (power), P8 VSS59 (power), P9 VSS60 (power), P10 VSS61 (power), P11 VSS62 (power), P12 VSS63 (power), P13 VSS64 (power), P14 VSS65 (power), P15 VSS66 (power), P16 VSS67 (power), R8 VSS68 (power), R9 VSS69 (power), R10 VSS70 (power), R11 VSS71 (power), R12 VSS72 (power), R13 VSS73 (power), R14 VSS74 (power), R15 VSS75 (power), R16 VSS76 (power), T8 VSS77 (power), T9 VSS78 (power), T10 VSS79 (power), T11 VSS80 (power), T12 VSS81 (power), T13 VSS82 (power), T14 VSS83 (power), T15 VSS84 (power), T16 VSS85 (power)

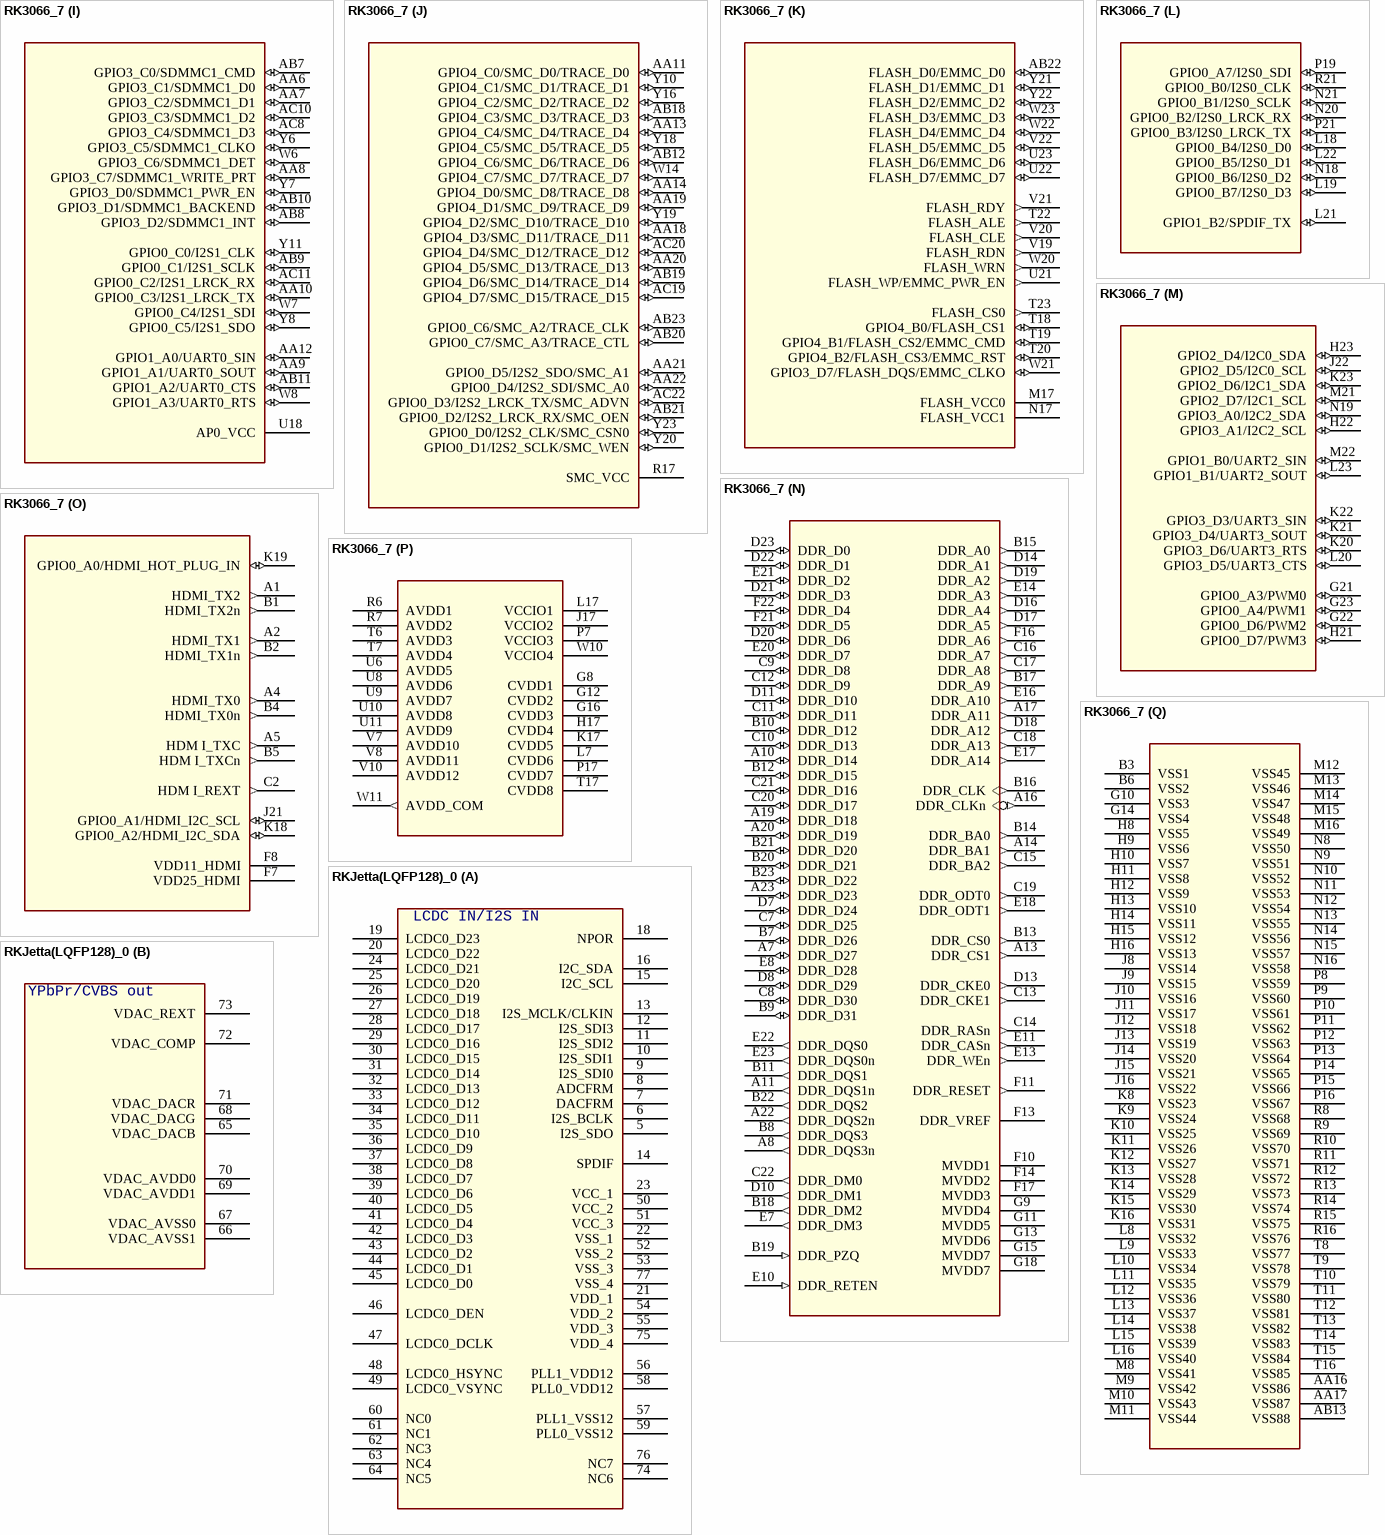
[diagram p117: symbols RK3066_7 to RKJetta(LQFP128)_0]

## RK3066_7
designator U?
Altium-Right: 160; Altium-Bottom: 130; Altium-Bottom1: 280; Altium-Right2: 180; Altium-Bottom2: 310; Altium-Bottom3: 270; Altium-Right4: 120; Altium-Bottom4: 140; Altium-Bottom5: 230; Altium-Bottom6: 530; Altium-Right7: 150; Altium-Bottom7: 250; Altium-Right8: 110; Altium-Bottom8: 170; Altium-Right9: 100; Altium-Bottom9: 470; Altium-Right10: 80; Altium-Bottom10: 350; Altium-Right11: 200; Altium-Bottom11: 190
footprint BGA453
part A pins: C3 LCD0_DEN (out), C4 LCD0_DCLK (out), C5 LCD0_VSYNC (out), C6 LCD0_HSYNC (out), D1 LCD0_D6 (out), D2 LCD0_D5 (out), D3 LCD0_D4 (out), D4 LCD0_D3 (out), D5 LCD0_D2 (out), D6 LCD0_D1 (out), E1 LCD0_D10 (out), E2 LCD0_D7 (out), E3 LCD0_D9 (out), E4 LCD0_D8 (out), E6 LCD0_D0 (out), F2 LCD0_D13 (out), F3 LCD0_D12 (out), F4 LCD0_D14 (out), F5 LCD0_D11 (out), G1 LCD0_D20 (out), G2 LCD0_D19 (out), G3 LCD0_D18 (out), G4 LCD0_D17 (out), G5 LCD0_D16 (out), G6 LCD0_D15 (out), H1 LCD0_D21 (out), H5 LCD0_D22 (out), H6 LCD0_D23 (out), H7 LCD0_VCC1 (power), J7 LCD0_VCC0 (power)
part B pins: H2 GPIO2_A0/LCD1_D0/SMC_A4 (io), H3 GPIO2_A1/LCD1_D1/SMC_A5 (io), H4 GPIO2_A2/LCD1_D2/SMC_A6 (io), J2 GPIO2_B7/LCD1_D14/SMC_A19/TS_D7 (io), J3 GPIO2_B6/LCD1_D14/SMC_A18/TS_SYNC (io), K1 GPIO2_C2/LCD1_D18/SMC_BIS_N1/TS_D5 (io), K2 GPIO2_C1/LCD1_D17/SMC_BIS_N0/TS_D6 (io), K3 GPIO2_B5/LCD1_D13/SMC_A17/TS_VALID (io), K4 GPIO2_C0/LCD1_D16/GPS_CLK/TS_CLKO (io), K7 LCD1_VCC (power), L1 GPIO2_C5/LCD1_D21/SPI1_RXD/TS_D2 (io), L2 GPIO2_C4/LCD1_D20/SPI1_CSN0/TS_D1 (io), L3 GPIO2_C3/LCD1_D19/SPI1_CLK/TS_D0 (io), L4 GPIO2_C7/LCD1_D23/SPI1_CSN1/TS_D4 (io), M2 GPIO2_C6/LCD1_D22/SPI1_RXD/TS_D3 (io)
part C pins: K5 CIF0_D5 (in), K6 CIF0_D2 (in), L5 CIF0_D9 (in), L6 CIF0_CLKIN (in), M3 CIF0_D8 (in), M7 CIF0_VCC (power), N1 CIF0_D4 (in), N2 CIF0_D3 (in), N3 CIF0_D7 (in), N4 GPIO1_B4/CIF0_D0 (io), N5 GPIO1_B3/CIF0_CLKO (io), N6 GPIO1_B5/CIF0_D1 (io), P1 CIF0_D6 (in), P2 CIF0_VSYNC (in), P3 CIF0_HREF (in), P4 GPIO1_B6/CIF0_D10 (io), P5 GPIO3_A3/I2C3_SCL (io), R2 GPIO3_A2/I2C3_SDA (io), R3 GPIO1_B7/CIF0_D11 (io)
part D pins: N7 CIF1_VCC (power), T1 GPIO1_C5/CIF1_D7/RMII_CRS_DVALID (io), T2 GPIO1_C0/CIF1_D2/RMII_CLKO (io), T3 GPIO1_C2/CIF1_D4/RMII_TXD1 (io), T4 GPIO1_C1/CIF1_D3/RMII_TX_EN (io), T5 GPIO1_C7/CIF1_D9/RMII_RXD0 (io), U1 GPIO1_D2/CIF1_CLKIN (io), U2 GPIO1_C4/CIF1_D6/RMII_RX_ERR (io), U3 GPIO1_C3/CIF1_D5/RMII_TXD0 (io), U4 GPIO1_D0/CIF1_VSYNC/MII_MD (io), U5 GPIO3_A5/I2C4_SCL (io), V2 GPIO1_D7/CIF1_CLKO (io), V3 GPIO1_C6/CIF1_D8/RMII_RXD1 (io), V4 GPIO1_D1/CIF1_HREF/MII_MDCLK (io), V5 GPIO3_A4/I2C4_SDA (io), W4 GPIO1_D6/CIF1_D11 (io)
part E pins: AA2 GPIO6_A4, AA3 GPIO6_A5, AA15 PVCC_3V3 (power), AB1 GPIO6_B0, AB2 GPIO6_B1, AB3 GPIO6_A1, AB4 GPIO6_A7, AB14 XOUT24M (out), AC1 GPIO6_A0, AC2 GPIO6_A3, AC4 GPIO6_A2, AC5 GPIO6_A6, AC13 DDRIO_RET_EN (out), AC14 XIN24M (in), U12 AVSS_APLL (power), U13 AVSS_DPLL (power), U14 AVSS_C/GPLL (power), V11 APLL_1V1 (power), V13 DPLL_1V1 (power), V14 C/GPLL_1V1 (power), V17 EFUSE (in), W13 PVDD_1V1 (power), Y1 CPU_PWROFF (out), Y2 CORE_PWROFF (out), Y3 DDRIO_PWROFF (out), Y4 GPIO6_B2, Y5 GPIO6_B3, Y13 CLKIN_32K (in), Y14 NPOR (in)
part F pins: AB15 HOST_RKELVIN (out), AB16 OTG_DM (io), AB17 HOST_DM (io), AC16 OTG_DP (io), AC17 HOST_DP (io), F19 GPIO0_A6/HOST_DRV (io), F20 TDO (out), G19 TDI/CPR_BYPASS (in), G20 TRSTN (in), H18 TCK/HSSCAN_SHIFT_CLOCK (in), H19 TMS/PLL_BYPASS (io), H20 RECOVER (in), P20 GPIO0_A5/OTG_DRV (io), U15 USBVDD_1V1 (power), U16 USBVDD_2V5 (power), V16 USBVDD_3V3 (power), W1 SARADC_ANI0 (in), W2 SARADC_ANI2 (in), W3 SARADC_ANI1 (in), W16 OTG_RKELVIN (out), W17 OTG_VBUS (in), Y17 OTG_ID (in)
part G pins: AA4 GPIO1_A4/UART1_RX/SPI0_CSN0 (io), AA5 GPIO4_B7/SPI0_CSN1 (io), AB5 GPIO1_A5/UART1_TX/SPI0_CLK (io), AB6 GPIO1_A6/UART1_CTSN/SPI0_RXD (io), AC7 GPIO1_A7/UART1_RTSN/SPI0_TXD (io), W18 AP1_VCC (power)
part H pins: AC23 GPIO3_B6/SDMMC0_DET (io), N22 GPIO3_B4/SDMMC0_D2 (io), N23 GPIO3_B5/SDMMC0_D3 (io), P18 GPIO3_A6/SDMMC0_RSTNO (io), P22 GPIO3_B3/SDMMC0_D1 (io), P23 GPIO3_B7/SDMMC0_WRITE_PRT (io), R22 GPIO3_A7/SDMMC0_PWR_EN (io), T21 GPIO3_B0/SDMMC0_CLKOUT (io), U19 GPIO3_B2/SDMMC0_D0 (io), U20 GPIO3_B1/SDMMC0_CMD (io)
part I pins: AA6 GPIO3_C1/SDMMC1_D0 (io), AA7 GPIO3_C2/SDMMC1_D1 (io), AA8 GPIO3_C7/SDMMC1_WRITE_PRT (io), AA9 GPIO1_A1/UART0_SOUT (io), AA10 GPIO0_C3/I2S1_LRCK_TX (io), AA12 GPIO1_A0/UART0_SIN (io), AB7 GPIO3_C0/SDMMC1_CMD (io), AB8 GPIO3_D2/SDMMC1_INT (io), AB9 GPIO0_C1/I2S1_SCLK (io), AB10 GPIO3_D1/SDMMC1_BACKEND (io), AB11 GPIO1_A2/UART0_CTS (io), AC8 GPIO3_C4/SDMMC1_D3 (io), AC10 GPIO3_C3/SDMMC1_D2 (io), AC11 GPIO0_C2/I2S1_LRCK_RX (io), U18 AP0_VCC (power), W6 GPIO3_C6/SDMMC1_DET (io), W7 GPIO0_C4/I2S1_SDI (io), W8 GPIO1_A3/UART0_RTS (io), Y6 GPIO3_C5/SDMMC1_CLKO (io), Y7 GPIO3_D0/SDMMC1_PWR_EN (io), Y8 GPIO0_C5/I2S1_SDO (io), Y11 GPIO0_C0/I2S1_CLK (io)
part J pins: AA11 GPIO4_C0/SMC_D0/TRACE_D0 (io), AA13 GPIO4_C4/SMC_D4/TRACE_D4 (io), AA14 GPIO4_D0/SMC_D8/TRACE_D8 (io), AA18 GPIO4_D3/SMC_D11/TRACE_D11 (io), AA19 GPIO4_D1/SMC_D9/TRACE_D9 (io), AA20 GPIO4_D5/SMC_D13/TRACE_D13 (io), AA21 GPIO0_D5/I2S2_SDO/SMC_A1 (io), AA22 GPIO0_D4/I2S2_SDI/SMC_A0 (io), AB12 GPIO4_C6/SMC_D6/TRACE_D6 (io), AB18 GPIO4_C3/SMC_D3/TRACE_D3 (io), AB19 GPIO4_D6/SMC_D14/TRACE_D14 (io), AB20 GPIO0_C7/SMC_A3/TRACE_CTL (io), AB21 GPIO0_D2/I2S2_LRCK_RX/SMC_OEN (io), AB23 GPIO0_C6/SMC_A2/TRACE_CLK (io), AC19 GPIO4_D7/SMC_D15/TRACE_D15 (io), AC20 GPIO4_D4/SMC_D12/TRACE_D12 (io), AC22 GPIO0_D3/I2S2_LRCK_TX/SMC_ADVN (io), R17 SMC_VCC (power), W14 GPIO4_C7/SMC_D7/TRACE_D7 (io), Y10 GPIO4_C1/SMC_D1/TRACE_D1 (io), Y16 GPIO4_C2/SMC_D2/TRACE_D2 (io), Y18 GPIO4_C5/SMC_D5/TRACE_D5 (io), Y19 GPIO4_D2/SMC_D10/TRACE_D10 (io), Y20 GPIO0_D1/I2S2_SCLK/SMC_WEN (io), Y23 GPIO0_D0/I2S2_CLK/SMC_CSN0 (io)
part K pins: AB22 FLASH_D0/EMMC_D0 (io), M17 FLASH_VCC0 (power), N17 FLASH_VCC1 (power), T18 GPIO4_B0/FLASH_CS1 (io), T19 GPIO4_B1/FLASH_CS2/EMMC_CMD (io), T20 GPIO4_B2/FLASH_CS3/EMMC_RST (io), T22 FLASH_ALE (out), T23 FLASH_CS0 (out), U21 FLASH_WP/EMMC_PWR_EN (out), U22 FLASH_D7/EMMC_D7 (io), U23 FLASH_D6/EMMC_D6 (io), V19 FLASH_RDN (out), V20 FLASH_CLE (out), V21 FLASH_RDY (out), V22 FLASH_D5/EMMC_D5 (io), W20 FLASH_WRN (out), W21 GPIO3_D7/FLASH_DQS/EMMC_CLKO (io), W22 FLASH_D4/EMMC_D4 (io), W23 FLASH_D3/EMMC_D3 (io), Y21 FLASH_D1/EMMC_D1 (io), Y22 FLASH_D2/EMMC_D2 (io)
part L pins: L18 GPIO0_B4/I2S0_D0 (io), L19 GPIO0_B7/I2S0_D3 (io), L21 GPIO1_B2/SPDIF_TX (io), L22 GPIO0_B5/I2S0_D1 (io), N18 GPIO0_B6/I2S0_D2 (io), N20 GPIO0_B2/I2S0_LRCK_RX (io), N21 GPIO0_B1/I2S0_SCLK (io), P19 GPIO0_A7/I2S0_SDI (io), P21 GPIO0_B3/I2S0_LRCK_TX (io), R21 GPIO0_B0/I2S0_CLK (io)
part M pins: G21 GPIO0_A3/PWM0 (io), G22 GPIO0_D6/PWM2 (io), G23 GPIO0_A4/PWM1 (io), H21 GPIO0_D7/PWM3 (io), H22 GPIO3_A1/I2C2_SCL (io), H23 GPIO2_D4/I2C0_SDA (io), J22 GPIO2_D5/I2C0_SCL (io), K20 GPIO3_D6/UART3_RTS (io), K21 GPIO3_D4/UART3_SOUT (io), K22 GPIO3_D3/UART3_SIN (io), K23 GPIO2_D6/I2C1_SDA (io), L20 GPIO3_D5/UART3_CTS (io), L23 GPIO1_B1/UART2_SOUT (io), M21 GPIO2_D7/I2C1_SCL (io), M22 GPIO1_B0/UART2_SIN (io), N19 GPIO3_A0/I2C2_SDA (io)
part N pins: A7 DDR_D27 (io), A8 DDR_DQS3n (out), A10 DDR_D14 (io), A11 DDR_DQS1n (out), A13 DDR_CS1 (out), A14 DDR_BA1 (out), A16 DDR_CLKn (out), A17 DDR_A11 (out), A19 DDR_D18 (io), A20 DDR_D19 (io), A22 DDR_DQS2n (out), A23 DDR_D23 (io), B7 DDR_D26 (io), B8 DDR_DQS3 (out), B9 DDR_D31 (io), B10 DDR_D12 (io), B11 DDR_DQS1 (out), B12 DDR_D15 (io), B13 DDR_CS0 (out), B14 DDR_BA0 (out), B15 DDR_A0 (out), B16 DDR_CLK (out), B17 DDR_A9 (out), B18 DDR_DM2 (out), B19 DDR_PZQ (in), B20 DDR_D21 (io), B21 DDR_D20 (io), B22 DDR_DQS2 (out), B23 DDR_D22 (io), C7 DDR_D25 (io), C8 DDR_D30 (io), C9 DDR_D8 (io), C10 DDR_D13 (io), C11 DDR_D11 (io), C12 DDR_D9 (io), C13 DDR_CKE1 (out), C14 DDR_RASn (out), C15 DDR_BA2 (out), C16 DDR_A7 (out), C17 DDR_A8 (out), C18 DDR_A13 (out), C19 DDR_ODT0 (out), C20 DDR_D17 (io), C21 DDR_D16 (io), C22 DDR_DM0 (out), D7 DDR_D24 (io), D8 DDR_D29 (io), D10 DDR_DM1 (out), D11 DDR_D10 (io), D13 DDR_CKE0 (out), D14 DDR_A1 (out), D16 DDR_A4 (out), D17 DDR_A5 (out), D18 DDR_A12 (out), D19 DDR_A2 (out), D20 DDR_D6 (io), D21 DDR_D3 (io), D22 DDR_D1 (io), D23 DDR_D0 (io), E7 DDR_DM3 (out), E8 DDR_D28 (io), E10 DDR_RETEN (in), E11 DDR_CASn (out), E13 DDR_WEn (out), E14 DDR_A3 (out), E16 DDR_A10 (out), E17 DDR_A14 (out), E18 DDR_ODT1 (out), E20 DDR_D7 (io), E21 DDR_D2 (io), E22 DDR_DQS0 (out), E23 DDR_DQS0n (out), F10 MVDD1 (power), F11 DDR_RESET (out), F13 DDR_VREF (power), F14 MVDD2 (power), F16 DDR_A6 (out), F17 MVDD3 (power), F21 DDR_D5 (io), F22 DDR_D4 (io), G9 MVDD4 (power), G11 MVDD5 (power), G13 MVDD6 (power), G15 MVDD7 (power), G18 MVDD7 (power)
part O pins: A1 HDMI_TX2 (out), A2 HDMI_TX1 (out), A4 HDMI_TX0 (out), A5 HDM I_TXC (out), B1 HDMI_TX2n (out), B2 HDMI_TX1n (out), B4 HDMI_TX0n (out), B5 HDM I_TXCn (out), C2 HDM I_REXT (out), F7 VDD25_HDMI (power), F8 VDD11_HDMI (power), J21 GPIO0_A1/HDMI_I2C_SCL (io), K18 GPIO0_A2/HDMI_I2C_SDA (io), K19 GPIO0_A0/HDMI_HOT_PLUG_IN (io)
part P pins: G8 CVDD1 (power), G12 CVDD2 (power), G16 CVDD3 (power), H17 CVDD4 (power), J17 VCCIO2 (power), K17 CVDD5 (power), L7 CVDD6 (power), L17 VCCIO1 (power), P7 VCCIO3 (power), P17 CVDD7 (power), R6 AVDD1 (power), R7 AVDD2 (power), T6 AVDD3 (power), T7 AVDD4 (power), T17 CVDD8 (power), U6 AVDD5 (power), U8 AVDD6 (power), U9 AVDD7 (power), U10 AVDD8 (power), U11 AVDD9 (power), V7 AVDD10 (power), V8 AVDD11 (power), V10 AVDD12 (power), W10 VCCIO4 (power), W11 AVDD_COM (out)
part Q pins: AA16 VSS86 (power), AA17 VSS87 (power), AB13 VSS88 (power), B3 VSS1 (power), B6 VSS2 (power), G10 VSS3 (power), G14 VSS4 (power), H8 VSS5 (power), H9 VSS6 (power), H10 VSS7 (power), H11 VSS8 (power), H12 VSS9 (power), H13 VSS10 (power), H14 VSS11 (power), H15 VSS12 (power), H16 VSS13 (power), J8 VSS14 (power), J9 VSS15 (power), J10 VSS16 (power), J11 VSS17 (power), J12 VSS18 (power), J13 VSS19 (power), J14 VSS20 (power), J15 VSS21 (power), J16 VSS22 (power), K8 VSS23 (power), K9 VSS24 (power), K10 VSS25 (power), K11 VSS26 (power), K12 VSS27 (power), K13 VSS28 (power), K14 VSS29 (power), K15 VSS30 (power), K16 VSS31 (power), L8 VSS32 (power), L9 VSS33 (power), L10 VSS34 (power), L11 VSS35 (power), L12 VSS36 (power), L13 VSS37 (power), L14 VSS38 (power), L15 VSS39 (power), L16 VSS40 (power), M8 VSS41 (power), M9 VSS42 (power), M10 VSS43 (power), M11 VSS44 (power), M12 VSS45 (power), M13 VSS46 (power), M14 VSS47 (power), M15 VSS48 (power), M16 VSS49 (power), N8 VSS50 (power), N9 VSS51 (power), N10 VSS52 (power), N11 VSS53 (power), N12 VSS54 (power), N13 VSS55 (power), N14 VSS56 (power), N15 VSS57 (power), N16 VSS58 (power), P8 VSS59 (power), P9 VSS60 (power), P10 VSS61 (power), P11 VSS62 (power), P12 VSS63 (power), P13 VSS64 (power), P14 VSS65 (power), P15 VSS66 (power), P16 VSS67 (power), R8 VSS68 (power), R9 VSS69 (power), R10 VSS70 (power), R11 VSS71 (power), R12 VSS72 (power), R13 VSS73 (power), R14 VSS74 (power), R15 VSS75 (power), R16 VSS76 (power), T8 VSS77 (power), T9 VSS78 (power), T10 VSS79 (power), T11 VSS80 (power), T12 VSS81 (power), T13 VSS82 (power), T14 VSS83 (power), T15 VSS84 (power), T16 VSS85 (power)

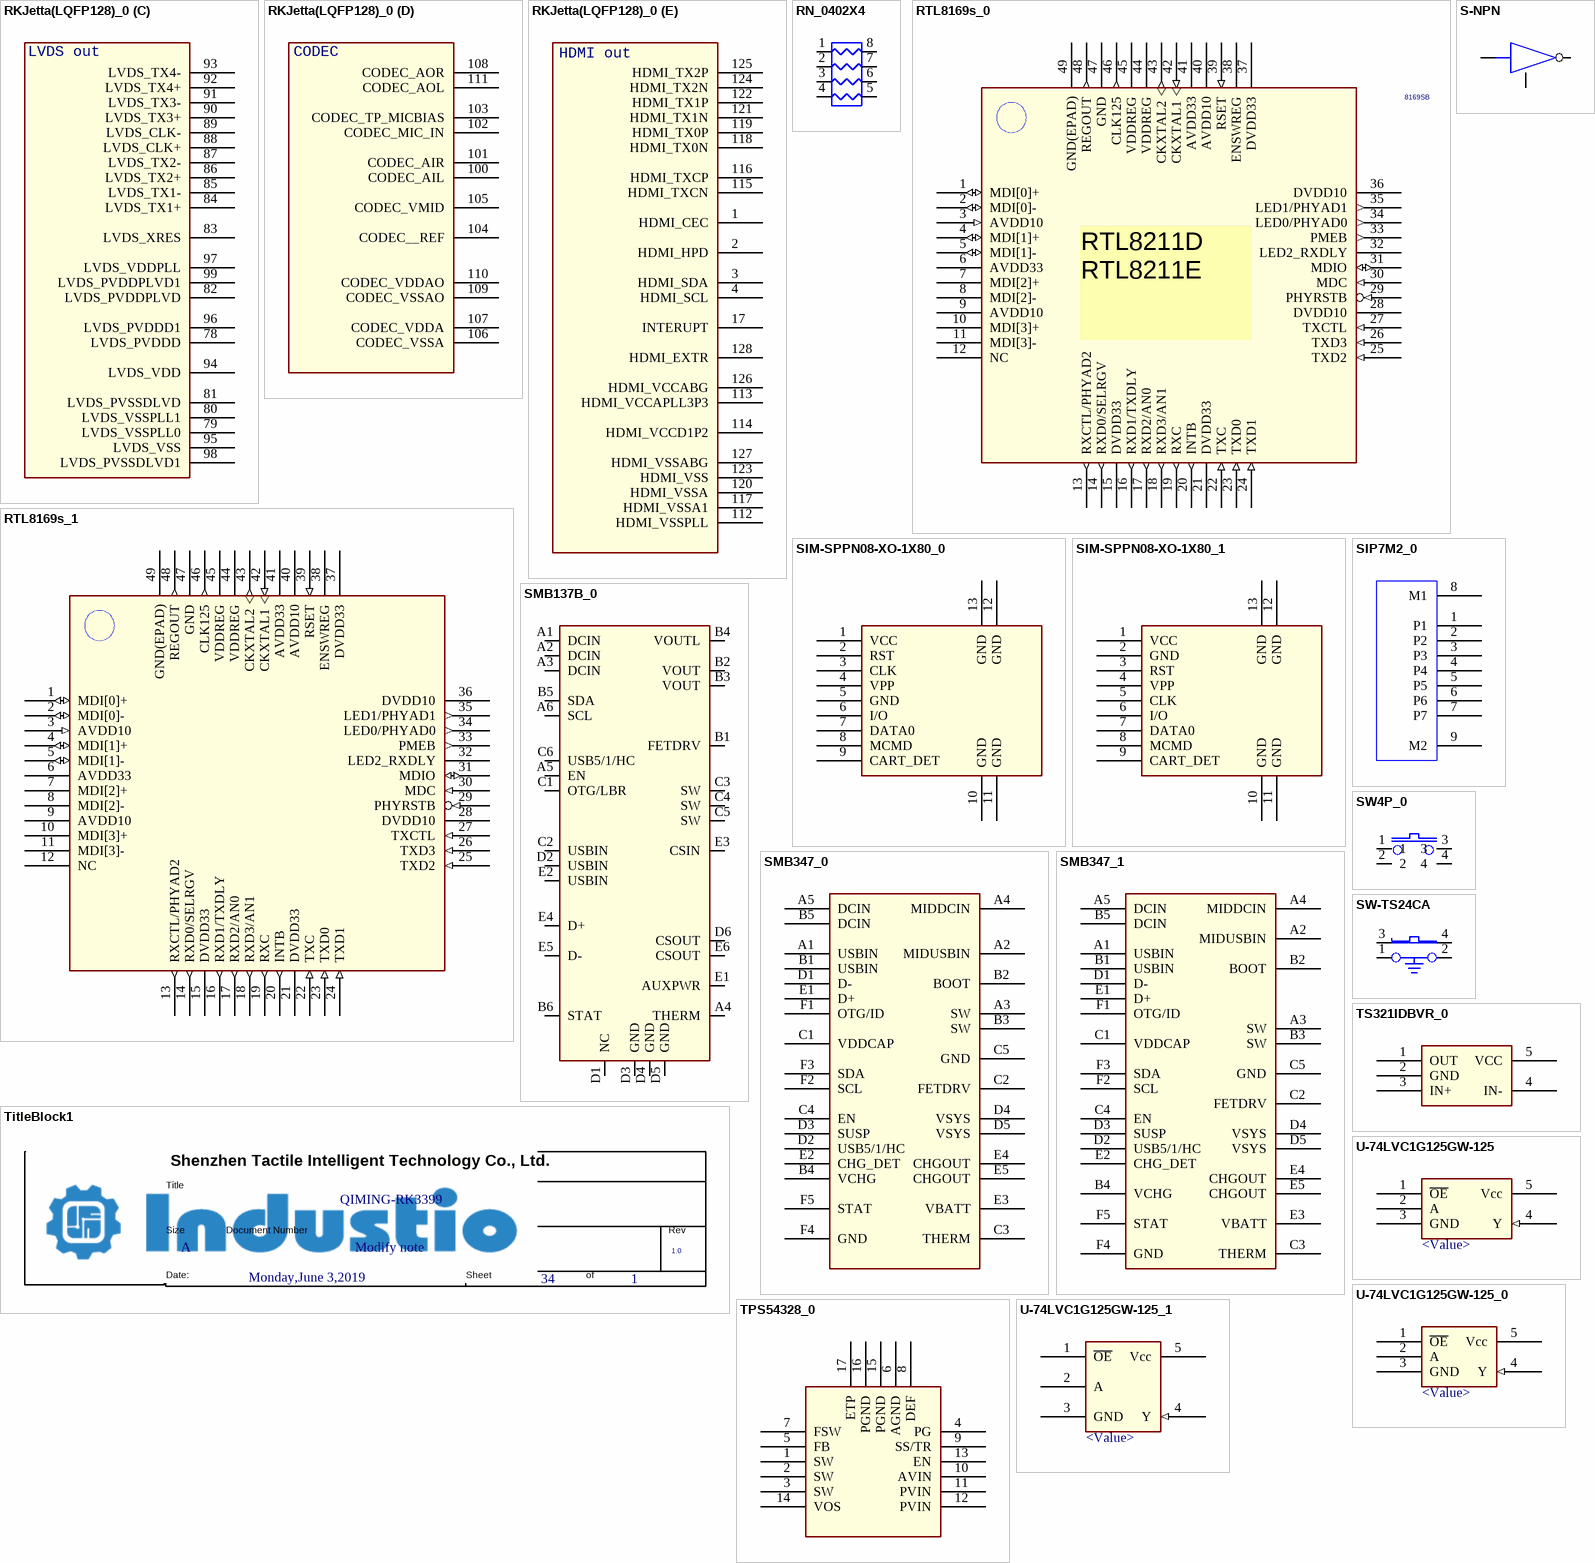
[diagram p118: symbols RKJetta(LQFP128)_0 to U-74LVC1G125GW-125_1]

## RKJetta(LQFP128)_0
designator U?
Altium-Right: 150; Altium-Bottom: 400; Altium-Right1: 120; Altium-Bottom1: 190; Altium-Right2: 110; Altium-Bottom2: 290; Altium-Bottom3: 220; Altium-Bottom4: 340
footprint LQFP128
part A pins: 5 I2S_SDO, 6 I2S_BCLK, 7 DACFRM, 8 ADCFRM, 9 I2S_SDI0, 10 I2S_SDI1, 11 I2S_SDI2, 12 I2S_SDI3, 13 I2S_MCLK/CLKIN, 14 SPDIF, 15 I2C_SCL, 16 I2C_SDA, 18 NPOR, 19 LCDC0_D23, 20 LCDC0_D22, 21 VDD_1, 22 VSS_1, 23 VCC_1, 24 LCDC0_D21, 25 LCDC0_D20, 26 LCDC0_D19, 27 LCDC0_D18, 28 LCDC0_D17, 29 LCDC0_D16, 30 LCDC0_D15, 31 LCDC0_D14, 32 LCDC0_D13, 33 LCDC0_D12, 34 LCDC0_D11, 35 LCDC0_D10, 36 LCDC0_D9, 37 LCDC0_D8, 38 LCDC0_D7, 39 LCDC0_D6, 40 LCDC0_D5, 41 LCDC0_D4, 42 LCDC0_D3, 43 LCDC0_D2, 44 LCDC0_D1, 45 LCDC0_D0, 46 LCDC0_DEN, 47 LCDC0_DCLK, 48 LCDC0_HSYNC, 49 LCDC0_VSYNC, 50 VCC_2, 51 VCC_3, 52 VSS_2, 53 VSS_3, 54 VDD_2, 55 VDD_3, 56 PLL1_VDD12, 57 PLL1_VSS12, 58 PLL0_VDD12, 59 PLL0_VSS12, 60 NC0, 61 NC1, 62 NC3, 63 NC4, 64 NC5, 74 NC6, 75 VDD_4, 76 NC7, 77 VSS_4
part B pins: 65 VDAC_DACB, 66 VDAC_AVSS1, 67 VDAC_AVSS0, 68 VDAC_DACG, 69 VDAC_AVDD1, 70 VDAC_AVDD0, 71 VDAC_DACR, 72 VDAC_COMP, 73 VDAC_REXT
part C pins: 78 LVDS_PVDDD, 79 LVDS_VSSPLL0, 80 LVDS_VSSPLL1, 81 LVDS_PVSSDLVD, 82 LVDS_PVDDPLVD, 83 LVDS_XRES, 84 LVDS_TX1+, 85 LVDS_TX1-, 86 LVDS_TX2+, 87 LVDS_TX2-, 88 LVDS_CLK+, 89 LVDS_CLK-, 90 LVDS_TX3+, 91 LVDS_TX3-, 92 LVDS_TX4+, 93 LVDS_TX4-, 94 LVDS_VDD, 95 LVDS_VSS, 96 LVDS_PVDDD1, 97 LVDS_VDDPLL, 98 LVDS_PVSSDLVD1, 99 LVDS_PVDDPLVD1
part D pins: 100 CODEC_AIL, 101 CODEC_AIR, 102 CODEC_MIC_IN, 103 CODEC_TP_MICBIAS, 104 CODEC__REF, 105 CODEC_VMID, 106 CODEC_VSSA, 107 CODEC_VDDA, 108 CODEC_AOR, 109 CODEC_VSSAO, 110 CODEC_VDDAO, 111 CODEC_AOL
part E pins: 1 HDMI_CEC, 2 HDMI_HPD, 3 HDMI_SDA, 4 HDMI_SCL, 17 INTERUPT, 112 HDMI_VSSPLL, 113 HDMI_VCCAPLL3P3, 114 HDMI_VCCD1P2, 115 HDMI_TXCN, 116 HDMI_TXCP, 117 HDMI_VSSA1, 118 HDMI_TX0N, 119 HDMI_TX0P, 120 HDMI_VSSA, 121 HDMI_TX1N, 122 HDMI_TX1P, 123 HDMI_VSS, 124 HDMI_TX2N, 125 HDMI_TX2P, 126 HDMI_VCCABG, 127 HDMI_VSSABG, 128 HDMI_EXTR

## RN_0402X4
designator RN?
Altium-Right: 20; Altium-Bottom: 50
pins: 1, 2, 3, 4, 5, 6, 7, 8

## RTL8169s_0
designator U?, comment 8169SB
Altium-Right: 250
pins: 1 MDI[0]+ (io), 2 MDI[0]- (io), 3 AVDD10 (in), 4 MDI[1]+ (io), 5 MDI[1]- (io), 6 AVDD33 (power), 7 MDI[2]+, 8 MDI[2]-, 9 AVDD10 (power), 10 MDI[3]+, 11 MDI[3]-, 12 NC, 13 RXCTL/PHYAD2 (out), 14 RXD0/SELRGV (out), 15 DVDD33 (power), 16 RXD1/TXDLY (out), 17 RXD2/AN0 (out), 18 RXD3/AN1 (out), 19 RXC (out), 20 INTB (out), 21 DVDD33 (power), 22 TXC (in), 23 TXD0 (in), 24 TXD1 (in), 25 TXD2 (in), 26 TXD3 (in), 27 TXCTL (in), 28 DVDD10 (power), 29 PHYRSTB (in), 30 MDC (in), 31 MDIO (io), 32 LED2_RXDLY, 33 PMEB (out), 34 LED0/PHYAD0 (out), 35 LED1/PHYAD1 (out), 36 DVDD10 (power), 37 DVDD33 (power), 38 ENSWREG, 39 RSET (in), 40 AVDD10 (power), 41 AVDD33 (power), 42 CKXTAL1 (in), 43 CKXTAL2 (out), 44 VDDREG (power), 45 VDDREG (power), 46 CLK125 (out), 47 GND, 48 REGOUT (out), 49 GND(EPAD)

## RTL8169s_1
designator U?
Altium-Right: 250
pins: 1 MDI[0]+ (io), 2 MDI[0]- (io), 3 AVDD10 (in), 4 MDI[1]+ (io), 5 MDI[1]- (io), 6 AVDD33 (power), 7 MDI[2]+, 8 MDI[2]-, 9 AVDD10 (power), 10 MDI[3]+, 11 MDI[3]-, 12 NC, 13 RXCTL/PHYAD2 (out), 14 RXD0/SELRGV (out), 15 DVDD33 (power), 16 RXD1/TXDLY (out), 17 RXD2/AN0 (out), 18 RXD3/AN1 (out), 19 RXC (out), 20 INTB (out), 21 DVDD33 (power), 22 TXC (in), 23 TXD0 (in), 24 TXD1 (in), 25 TXD2 (in), 26 TXD3 (in), 27 TXCTL (in), 28 DVDD10 (power), 29 PHYRSTB (in), 30 MDC (in), 31 MDIO (io), 32 LED2_RXDLY, 33 PMEB (out), 34 LED0/PHYAD0 (out), 35 LED1/PHYAD1 (out), 36 DVDD10 (power), 37 DVDD33 (power), 38 ENSWREG, 39 RSET (in), 40 AVDD10 (power), 41 AVDD33 (power), 42 CKXTAL1 (in), 43 CKXTAL2 (out), 44 VDDREG (power), 45 VDDREG (power), 46 CLK125 (out), 47 GND, 48 REGOUT (out), 49 GND(EPAD)

## S-NPN
designator Q?
Altium-Right: 40; Altium-Bottom: 20
pins: 1, 2, 3

## SIM-SPPN08-XO-1X80_0
designator J?
Altium-Right: 120; Altium-Bottom: 100
footprint SIM-SPPN08-XO-1X80
pins: 1 VCC, 2 RST, 3 CLK, 4 VPP, 5 GND, 6 I/O, 7 DATA0, 8 MCMD, 9 CART_DET, 10 GND, 11 GND, 12 GND, 13 GND

## SIM-SPPN08-XO-1X80_1
designator J?
Altium-Right: 120; Altium-Bottom: 100
footprint SIM-SPPN08-XO-1X80
pins: 1 VCC, 2 GND, 3 RST, 4 VPP, 5 CLK, 6 I/O, 7 DATA0, 8 MCMD, 9 CART_DET, 10 GND, 11 GND, 12 GND, 13 GND

## SIP7M2_0
designator J?, comment SIP7M2  (value not drawn)
PARTS: 1; DEVICE: 67491-1032; LEVEL: STD; PKG_TYPE: 9; CODE: 184999; OriginalSymbolOrigin: (10,130); Altium-Right: 40; Altium-Bottom: 120
pins: 1 P1, 2 P2, 3 P3, 4 P4, 5 P5, 6 P6, 7 P7, 8 M1, 9 M2

## SMB137B_0
designator U?
Altium-Right: 100; Altium-Bottom: 290
pins: A1 DCIN, A2 DCIN, A3 DCIN, A4 THERM, A5 EN, A6 SCL, B1 FETDRV, B2 VOUT, B3 VOUT, B4 VOUTL, B5 SDA, B6 STAT, C1 OTG/LBR, C2 USBIN, C3 SW, C4 SW, C5 SW, C6 USB5/1/HC, D1 NC, D2 USBIN, D3 GND, D4 GND, D5 GND, D6 CSOUT, E1 AUXPWR, E2 USBIN, E3 CSIN, E4 D+, E5 D-, E6 CSOUT

## SMB347_0
designator U?
Altium-Right: 100; Altium-Bottom: 250
footprint BGA30-3X2.5
pins: A1 USBIN, A2 MIDUSBIN, A3 SW, A4 MIDDCIN, A5 DCIN, B1 USBIN, B2 BOOT, B3 SW, B4 VCHG, B5 DCIN, C1 VDDCAP, C2 FETDRV, C3 THERM, C4 EN, C5 GND, D1 D-, D2 USB5/1/HC, D3 SUSP, D4 VSYS, D5 VSYS, E1 D+, E2 CHG_DET, E3 VBATT, E4 CHGOUT, E5 CHGOUT, F1 OTG/ID, F2 SCL, F3 SDA, F4 GND, F5 STAT

## SMB347_1
designator U?
Altium-Right: 100; Altium-Bottom: 250
footprint BGA30-3X2.5
pins: A1 USBIN, A2 MIDUSBIN, A3 SW, A4 MIDDCIN, A5 DCIN, B1 USBIN, B2 BOOT, B3 SW, B4 VCHG, B5 DCIN, C1 VDDCAP, C2 FETDRV, C3 THERM, C4 EN, C5 GND, D1 D-, D2 USB5/1/HC, D3 SUSP, D4 VSYS, D5 VSYS, E1 D+, E2 CHG_DET, E3 VBATT, E4 CHGOUT, E5 CHGOUT, F1 OTG/ID, F2 SCL, F3 SDA, F4 GND, F5 STAT

## SW4P_0
designator SW?
Altium-Right: 30
pins: 1, 2, 3, 4

## SW-TS24CA
designator SW?
Altium-Right: 30
pins: 1, 2, 3, 4

## TitleBlock1
designator *  Page Modify Date: Monday,June 3,2019  Doc: Modify note  RevCode: 1.0  Title: QIMING-RK3399  Page Size: A  Page Number: 34  Page Count: 1  (hidden comment: *)  (graphical)
Altium-Right: 455; Altium-Bottom: 91

## TPS54328_0
designator U?
Altium-Right: 90; Altium-Bottom: 100
footprint SOP8A
pins: 1 SW, 2 SW, 3 SW, 4 PG, 5 FB, 6 AGND, 7 FSW, 8 DEF, 9 SS/TR, 10 AVIN, 11 PVIN, 12 PVIN, 13 EN, 14 VOS, 15 PGND, 16 PGND, 17 ETP

## TS321IDBVR_0
designator U?
Altium-Right: 60; Altium-Bottom: 40
footprint SOT25
pins: 1 OUT, 2 GND, 3 IN+, 4 IN-, 5 VCC

## U-74LVC1G125GW-125
designator U?, comment <Value>
Altium-Right: 60; Altium-Bottom: 40
pins: 1 ~{OE}, 2 A (power), 3 GND, 4 Y (in), 5 Vcc

## U-74LVC1G125GW-125_0
designator U?, comment <Value>
Altium-Right: 50; Altium-Bottom: 40
pins: 1 ~{OE}, 2 A (power), 3 GND, 4 Y (in), 5 Vcc

## U-74LVC1G125GW-125_1
designator U?, comment <Value>
Altium-Right: 50; Altium-Bottom: 60
pins: 1 ~{OE}, 2 A (power), 3 GND, 4 Y (in), 5 Vcc

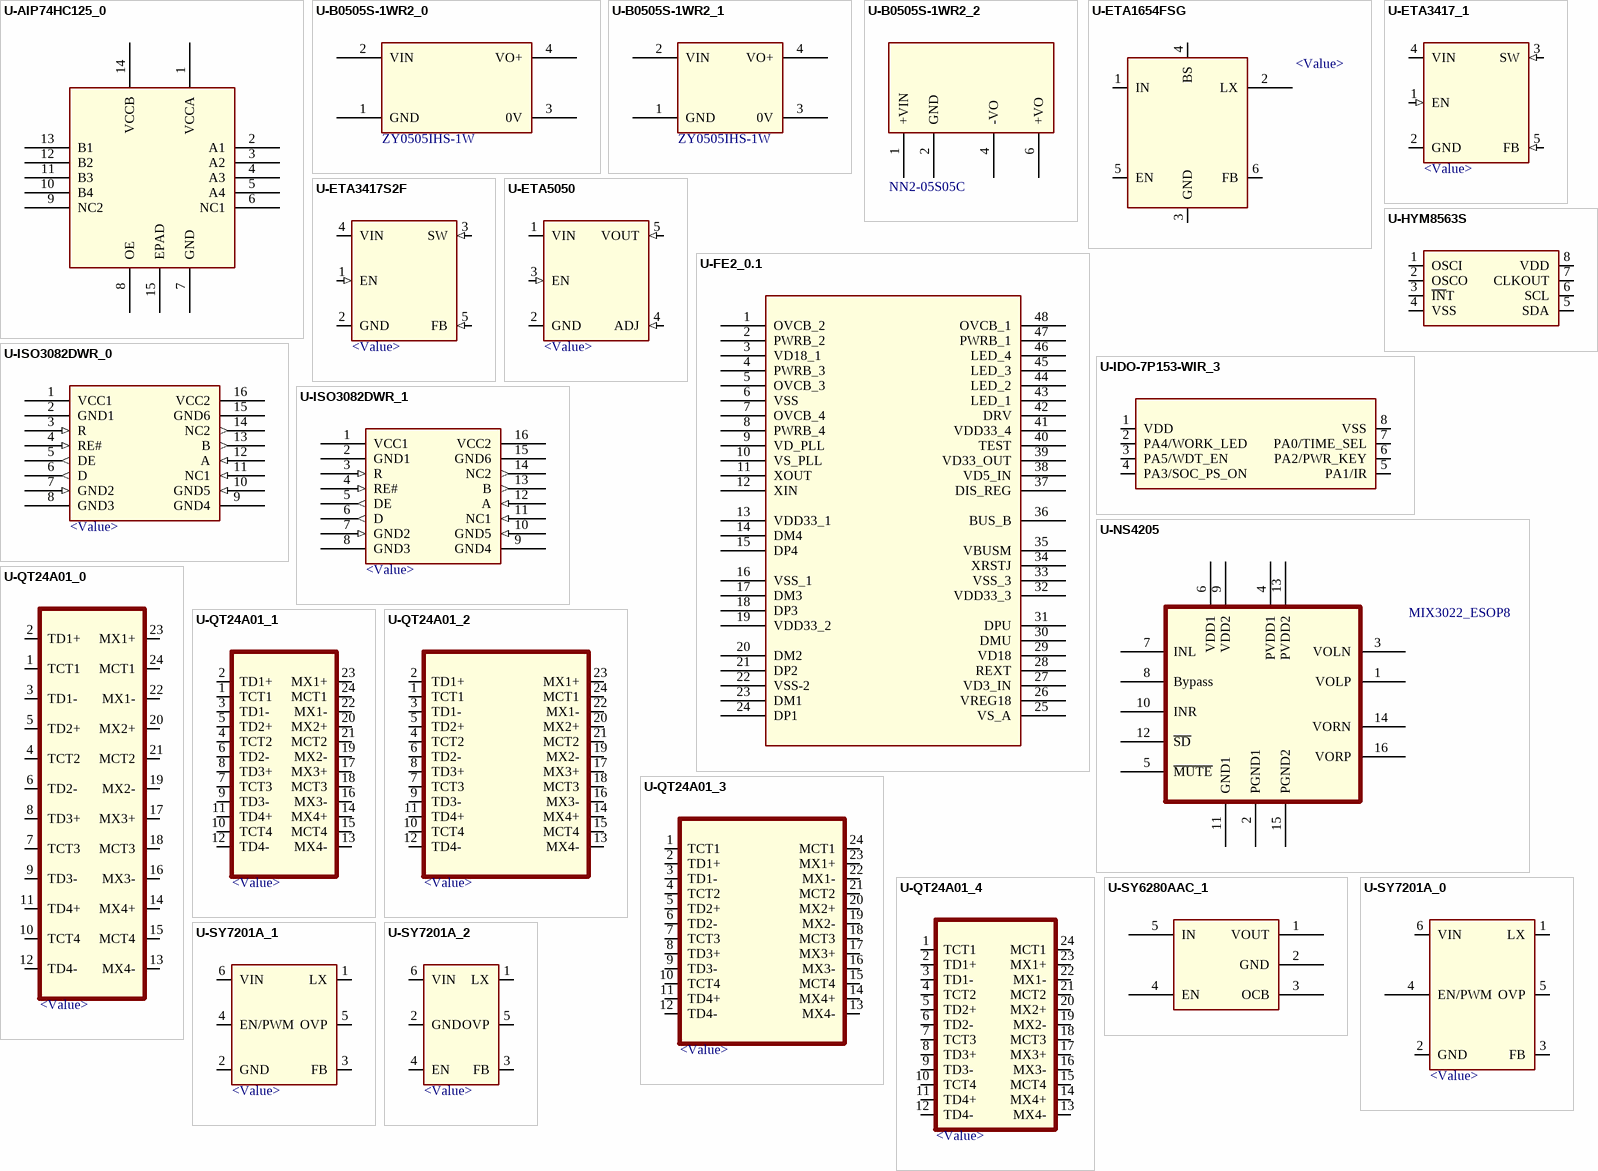
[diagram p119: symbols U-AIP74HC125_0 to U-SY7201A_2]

## U-AIP74HC125_0
designator U?
Altium-Right: 110; Altium-Bottom: 120
pins: 1 VCCA, 2 A1, 3 A2, 4 A3, 5 A4, 6 NC1, 7 GND, 8 OE, 9 NC2, 10 B4, 11 B3, 12 B2, 13 B1, 14 VCCB, 15 EPAD

## U-B0505S-1WR2_0
designator U?, comment ZY0505IHS-1W
Altium-Right: 100; Altium-Bottom: 60
pins: 1 GND, 2 VIN, 3 0V, 4 VO+

## U-B0505S-1WR2_1
designator U?, comment ZY0505IHS-1W
Altium-Right: 70; Altium-Bottom: 60
pins: 1 GND, 2 VIN, 3 0V, 4 VO+

## U-B0505S-1WR2_2
designator U?, comment NN2-05S05C
Altium-Right: 110; Altium-Bottom: 60
pins: 1 +VIN, 2 GND, 4 -VO, 6 +VO

## U-ETA1654FSG
designator U?, comment <Value>
Altium-Right: 80; Altium-Bottom: 100
pins: 1 IN, 2 LX, 3 GND, 4 BS, 5 EN, 6 FB

## U-ETA3417_1
designator U?, comment <Value>
Altium-Right: 70; Altium-Bottom: 80
pins: 1 EN (in), 2 GND (power), 3 SW (in), 4 VIN (power), 5 FB (in)

## U-ETA3417S2F
designator U?, comment <Value>
Altium-Right: 70; Altium-Bottom: 80
pins: 1 EN (in), 2 GND (power), 3 SW (in), 4 VIN (power), 5 FB (in)

## U-ETA5050
designator U?, comment <Value>
Altium-Right: 70; Altium-Bottom: 80
pins: 1 VIN (power), 2 GND (power), 3 EN (in), 4 ADJ (in), 5 VOUT (in)

## U-FE2_0.1
designator U?
Altium-Right: 170; Altium-Bottom: 300
pins: 1 OVCB_2, 2 PWRB_2, 3 VD18_1, 4 PWRB_3, 5 OVCB_3, 6 VSS (power), 7 OVCB_4, 8 PWRB_4, 9 VD_PLL, 10 VS_PLL, 11 XOUT, 12 XIN, 13 VDD33_1, 14 DM4, 15 DP4 (power), 16 VSS_1, 17 DM3, 18 DP3, 19 VDD33_2, 20 DM2 (power), 21 DP2, 22 VSS-2, 23 DM1, 24 DP1, 25 VS_A, 26 VREG18 (power), 27 VD3_IN, 28 REXT (power), 29 VD18, 30 DMU, 31 DPU (power), 32 VDD33_3, 33 VSS_3, 34 XRSTJ, 35 VBUSM, 36 BUS_B (power), 37 DIS_REG, 38 VD5_IN, 39 VD33_OUT, 40 TEST, 41 VDD33_4, 42 DRV (power), 43 LED_1, 44 LED_2, 45 LED_3, 46 LED_4, 47 PWRB_1, 48 OVCB_1

## U-HYM8563S
designator U?
Altium-Right: 90; Altium-Bottom: 50
pins: 1 OSCI, 2 OSCO, 3 ~{IN}T, 4 VSS, 5 SDA, 6 SCL, 7 CLKOUT, 8 VDD

## U-IDO-7P153-WIR_3
designator U?
Altium-Right: 160; Altium-Bottom: 60
pins: 1 VDD, 2 PA4/WORK_LED, 3 PA5/WDT_EN, 4 PA3/SOC_PS_ON, 5 PA1/IR, 6 PA2/PWR_KEY, 7 PA0/TIME_SEL, 8 VSS

## U-ISO3082DWR_0
designator U?, comment <Value>
Altium-Right: 100; Altium-Bottom: 90
pins: 1 VCC1 (power), 2 GND1 (power), 3 R (in), 4 RE# (in), 5 DE (out), 6 D (out), 7 GND2 (in), 8 GND3 (power), 9 GND4 (power), 10 GND5 (in), 11 NC1 (in), 12 A (in), 13 B (out), 14 NC2 (out), 15 GND6 (power), 16 VCC2 (power)

## U-ISO3082DWR_1
designator U?, comment <Value>
Altium-Right: 90
pins: 1 VCC1 (power), 2 GND1 (power), 3 R (in), 4 RE# (in), 5 DE (out), 6 D (out), 7 GND2 (in), 8 GND3 (power), 9 GND4 (power), 10 GND5 (in), 11 NC1 (in), 12 A (in), 13 B (out), 14 NC2 (out), 15 GND6 (power), 16 VCC2 (power)

## U-NS4205
designator U?, comment MIX3022_ESOP8
Altium-Right: 130
pins: 1 VOLP, 2 PGND1, 3 VOLN, 4 PVDD1, 5 ~{MUTE}, 6 VDD1, 7 INL, 8 Bypass, 9 VDD2, 10 INR, 11 GND1, 12 ~{SD}, 13 PVDD2, 14 VORN, 15 PGND2, 16 VORP

## U-QT24A01_0
designator U?, comment <Value>
Altium-Right: 70; Altium-Bottom: 260
pins: 1 TCT1, 2 TD1+, 3 TD1-, 4 TCT2, 5 TD2+, 6 TD2-, 7 TCT3, 8 TD3+, 9 TD3-, 10 TCT4, 11 TD4+, 12 TD4-, 13 MX4-, 14 MX4+, 15 MCT4, 16 MX3-, 17 MX3+, 18 MCT3, 19 MX2-, 20 MX2+, 21 MCT2, 22 MX1-, 23 MX1+, 24 MCT1

## U-QT24A01_1
designator U?, comment <Value>
Altium-Right: 70; Altium-Bottom: 150
pins: 1 TCT1, 2 TD1+, 3 TD1-, 4 TCT2, 5 TD2+, 6 TD2-, 7 TCT3, 8 TD3+, 9 TD3-, 10 TCT4, 11 TD4+, 12 TD4-, 13 MX4-, 14 MX4+, 15 MCT4, 16 MX3-, 17 MX3+, 18 MCT3, 19 MX2-, 20 MX2+, 21 MCT2, 22 MX1-, 23 MX1+, 24 MCT1

## U-QT24A01_2
designator U?, comment <Value>
Altium-Right: 110; Altium-Bottom: 150
pins: 1 TCT1, 2 TD1+, 3 TD1-, 4 TCT2, 5 TD2+, 6 TD2-, 7 TCT3, 8 TD3+, 9 TD3-, 10 TCT4, 11 TD4+, 12 TD4-, 13 MX4-, 14 MX4+, 15 MCT4, 16 MX3-, 17 MX3+, 18 MCT3, 19 MX2-, 20 MX2+, 21 MCT2, 22 MX1-, 23 MX1+, 24 MCT1

## U-QT24A01_3
designator U?, comment <Value>
Altium-Right: 110; Altium-Bottom: 150
pins: 1 TCT1, 2 TD1+, 3 TD1-, 4 TCT2, 5 TD2+, 6 TD2-, 7 TCT3, 8 TD3+, 9 TD3-, 10 TCT4, 11 TD4+, 12 TD4-, 13 MX4-, 14 MX4+, 15 MCT4, 16 MX3-, 17 MX3+, 18 MCT3, 19 MX2-, 20 MX2+, 21 MCT2, 22 MX1-, 23 MX1+, 24 MCT1

## U-QT24A01_4
designator U?, comment <Value>
Altium-Right: 80; Altium-Bottom: 140
pins: 1 TCT1, 2 TD1+, 3 TD1-, 4 TCT2, 5 TD2+, 6 TD2-, 7 TCT3, 8 TD3+, 9 TD3-, 10 TCT4, 11 TD4+, 12 TD4-, 13 MX4-, 14 MX4+, 15 MCT4, 16 MX3-, 17 MX3+, 18 MCT3, 19 MX2-, 20 MX2+, 21 MCT2, 22 MX1-, 23 MX1+, 24 MCT1

## U-SY6280AAC_1
designator U?
Altium-Right: 70; Altium-Bottom: 60
pins: 1 VOUT, 2 GND, 3 OCB, 4 EN, 5 IN

## U-SY7201A_0
designator U?, comment <Value>
Altium-Right: 70; Altium-Bottom: 100
pins: 1 LX, 2 GND, 3 FB, 4 EN/PWM, 5 OVP, 6 VIN

## U-SY7201A_1
designator U?, comment <Value>
Altium-Right: 70; Altium-Bottom: 80
pins: 1 LX, 2 GND, 3 FB, 4 EN/PWM, 5 OVP, 6 VIN

## U-SY7201A_2
designator U?, comment <Value>
Altium-Right: 50; Altium-Bottom: 80
pins: 1 LX, 2 GND, 3 FB, 4 EN, 5 OVP, 6 VIN

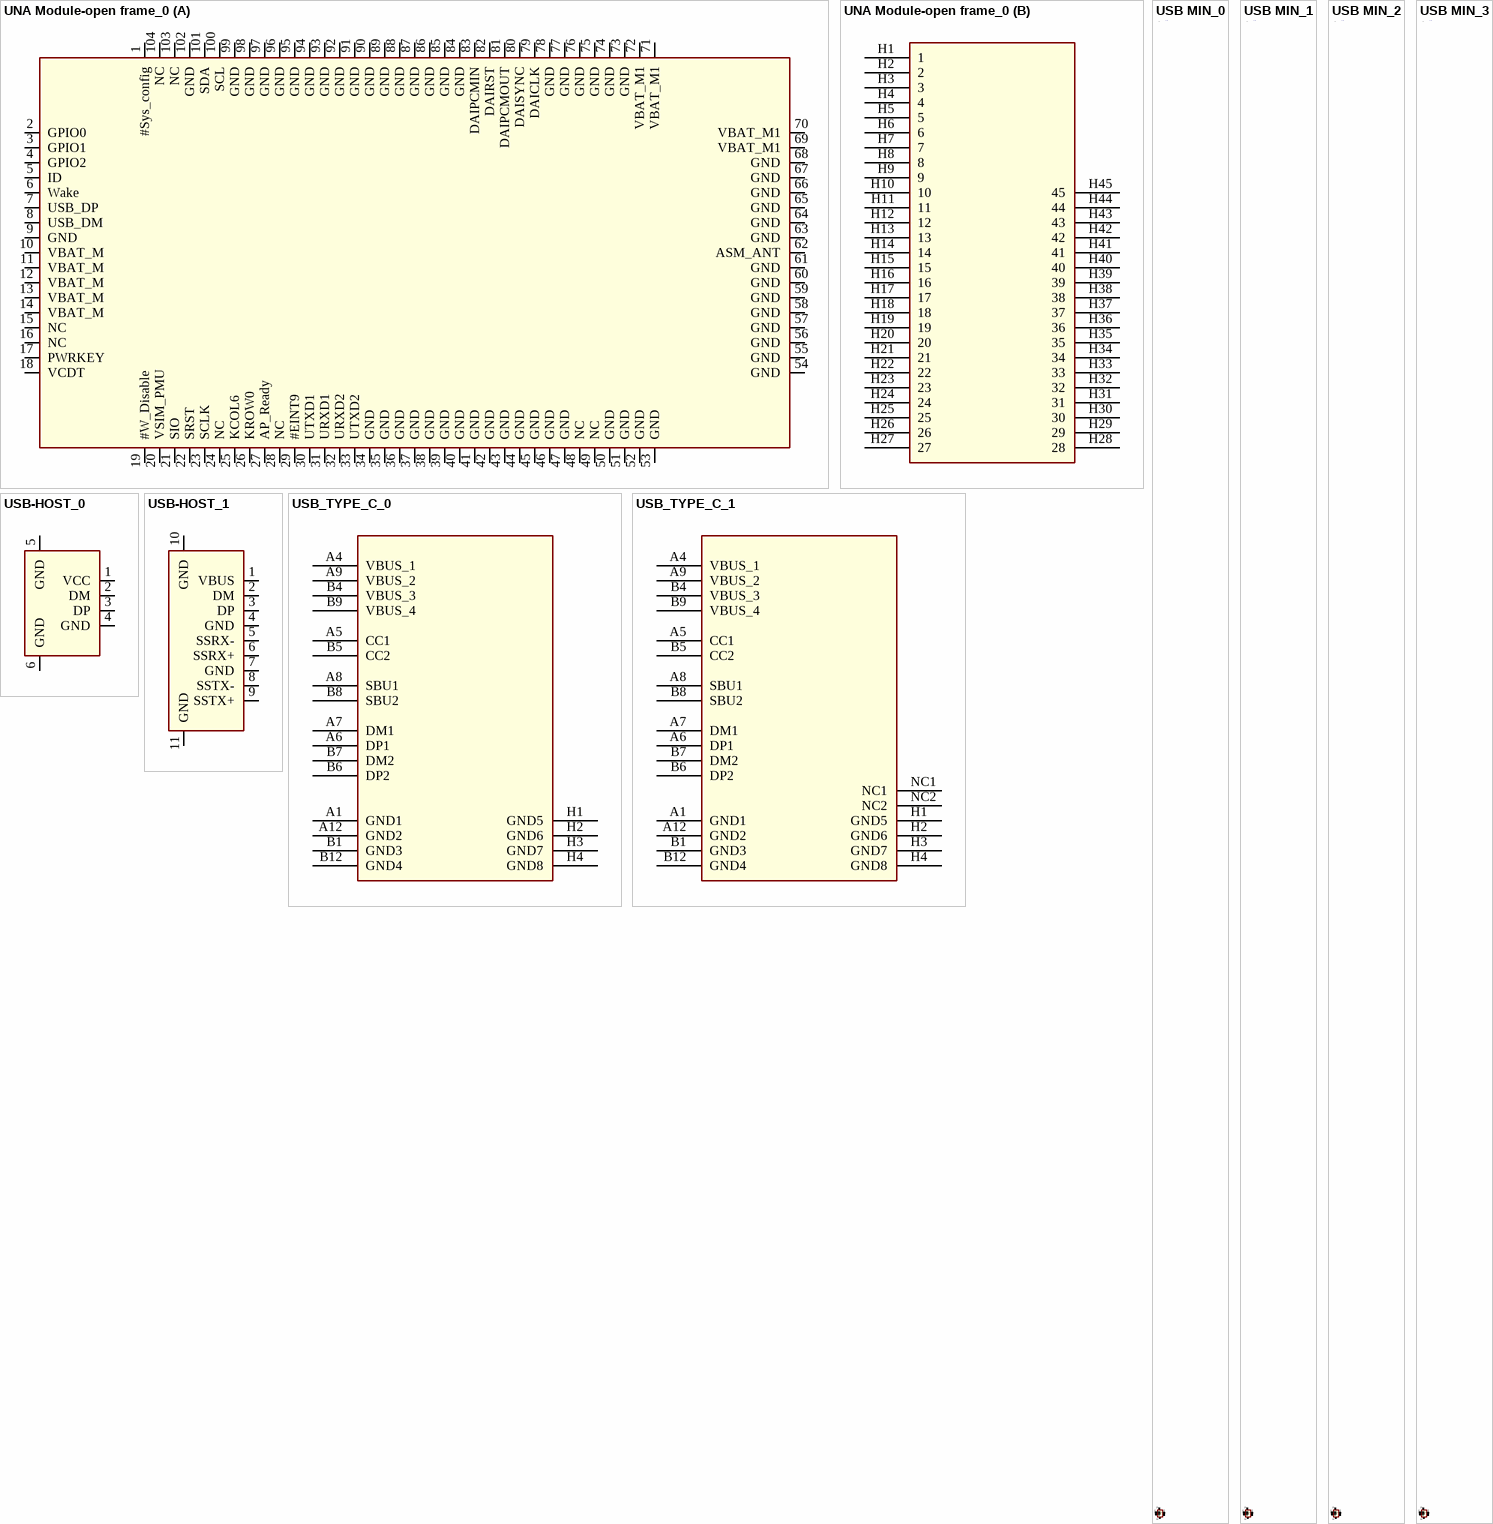
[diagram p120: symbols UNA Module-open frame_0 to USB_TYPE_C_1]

## UNA Module-open frame_0
designator U?
Altium-Right: 500; Altium-Bottom: 260; Altium-Right1: 110; Altium-Bottom1: 280
part A pins: 1 #Sys_config, 2 GPIO0, 3 GPIO1, 4 GPIO2, 5 ID, 6 Wake, 7 USB_DP, 8 USB_DM, 9 GND, 10 VBAT_M, 11 VBAT_M, 12 VBAT_M, 13 VBAT_M, 14 VBAT_M, 15 NC, 16 NC, 17 PWRKEY, 18 VCDT, 19 #W_Disable, 20 VSIM_PMU, 21 SIO, 22 SRST, 23 SCLK, 24 NC, 25 KCOL6, 26 KROW0, 27 AP_Ready, 28 NC, 29 #EINT9, 30 UTXD1, 31 URXD1, 32 URXD2, 33 UTXD2, 34 GND, 35 GND, 36 GND, 37 GND, 38 GND, 39 GND, 40 GND, 41 GND, 42 GND, 43 GND, 44 GND, 45 GND, 46 GND, 47 GND, 48 NC, 49 NC, 50 GND, 51 GND, 52 GND, 53 GND, 54 GND, 55 GND, 56 GND, 57 GND, 58 GND, 59 GND, 60 GND, 61 GND, 62 ASM_ANT, 63 GND, 64 GND, 65 GND, 66 GND, 67 GND, 68 GND, 69 VBAT_M1, 70 VBAT_M1, 71 VBAT_M1, 72 VBAT_M1, 73 GND, 74 GND, 75 GND, 76 GND, 77 GND, 78 GND, 79 DAICLK, 80 DAISYNC, 81 DAIPCMOUT, 82 DAIRST, 83 DAIPCMIN, 84 GND, 85 GND, 86 GND, 87 GND, 88 GND, 89 GND, 90 GND, 91 GND, 92 GND, 93 GND, 94 GND, 95 GND, 96 GND, 97 GND, 98 GND, 99 GND, 100 SCL, 101 SDA, 102 GND, 103 NC, 104 NC
part B pins: H1 1, H2 2, H3 3, H4 4, H5 5, H6 6, H7 7, H8 8, H9 9, H10 10, H11 11, H12 12, H13 13, H14 14, H15 15, H16 16, H17 17, H18 18, H19 19, H20 20, H21 21, H22 22, H23 23, H24 24, H25 25, H26 26, H27 27, H28 28, H29 29, H30 30, H31 31, H32 32, H33 33, H34 34, H35 35, H36 36, H37 37, H38 38, H39 39, H40 40, H41 41, H42 42, H43 43, H44 44, H45 45

## USB MIN_0
designator J?, comment USBmin
Altium-Right: 80; Altium-Bottom: 90
pins: 1 NC, 2 VBUS, 3 TD_DM, 4 DM, 5 NC (power), 6 DP, 7 NC, 8 ID, 9 NC, 10 GND, 11 GND, 12 GND, 13 GND, 14 GND

## USB MIN_1
designator J?, comment USBmin
Altium-Right: 80; Altium-Bottom: 90
pins: 1 NC, 2 VBUS, 3 TD_DM, 4 DM, 5 NC (power), 6 DP, 7 NC, 8 ID, 9 NC, 10 GND, 11 GND, 12 GND, 13 GND, 14 GND

## USB MIN_2
designator J?, comment USBmin
Altium-Right: 80; Altium-Bottom: 90
pins: 1 NC, 2 VBUS, 3 TD_DM, 4 DM, 5 NC, 6 DP, 7 NC, 8 ID, 9 NC, 10 GND, 11 GND, 12 GND, 13 GND, 14 GND

## USB MIN_3
designator J?, comment USBmin
Altium-Right: 80; Altium-Bottom: 90
pins: 1 NC, 2 VBUS, 3 TD_DM, 4 DM, 5 NC, 6 DP, 7 NC, 8 ID, 9 NC, 10 GND, 11 GND, 12 GND, 13 GND, 14 GND

## USB-HOST_0
designator J?
Altium-Right: 50; Altium-Bottom: 70
footprint USB-HOST
pins: 1 VCC, 2 DM, 3 DP, 4 GND, 5 GND, 6 GND

## USB-HOST_1
designator J?
Altium-Right: 50; Altium-Bottom: 120
footprint USB-HOST
pins: 1 VBUS, 2 DM, 3 DP, 4 GND, 5 SSRX-, 6 SSRX+, 7 GND, 8 SSTX-, 9 SSTX+, 10 GND, 11 GND

## USB_TYPE_C_0
designator J?
Altium-Right: 130; Altium-Bottom: 230
pins: A1 GND1, A4 VBUS_1, A5 CC1, A6 DP1, A7 DM1, A8 SBU1, A9 VBUS_2, A12 GND2, B1 GND3, B4 VBUS_3, B5 CC2, B6 DP2, B7 DM2, B8 SBU2, B9 VBUS_4, B12 GND4, H1 GND5, H2 GND6, H3 GND7, H4 GND8

## USB_TYPE_C_1
designator J?
Altium-Right: 130; Altium-Bottom: 230
pins: A1 GND1, A4 VBUS_1, A5 CC1, A6 DP1, A7 DM1, A8 SBU1, A9 VBUS_2, A12 GND2, B1 GND3, B4 VBUS_3, B5 CC2, B6 DP2, B7 DM2, B8 SBU2, B9 VBUS_4, B12 GND4, H1 GND5, H2 GND6, H3 GND7, H4 GND8, NC1, NC2

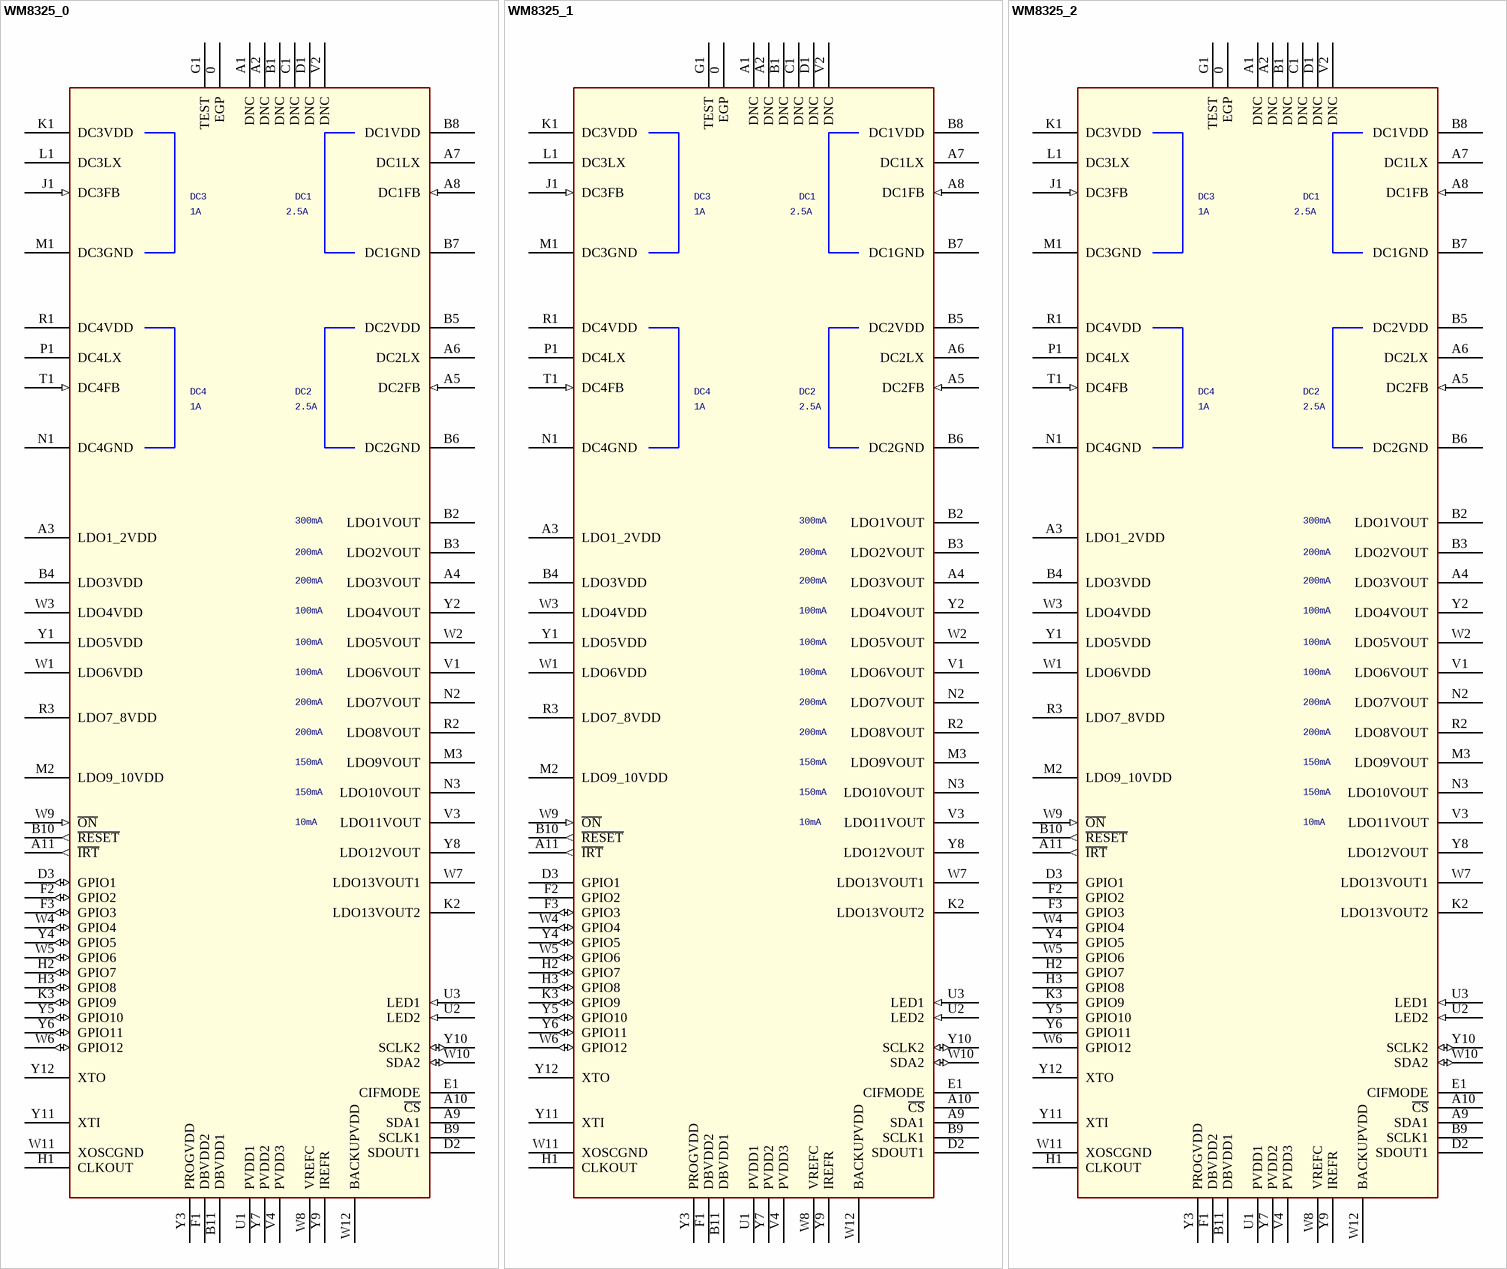
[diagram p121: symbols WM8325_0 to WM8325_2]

## WM8325_0
designator U?
Altium-Right: 240; Altium-Bottom: 740
footprint QFN81-8X8
pins: 0 EGP, A1 DNC, A2 DNC, A3 LDO1_2VDD (power), A4 LDO3VOUT (power), A5 DC2FB (in), A6 DC2LX (power), A7 DC1LX (power), A8 DC1FB (in), A9 SDA1, A10 ~{CS}, A11 ~{IRT} (out), B1 DNC, B2 LDO1VOUT (power), B3 LDO2VOUT (power), B4 LDO3VDD (power), B5 DC2VDD (power), B6 DC2GND (power), B7 DC1GND (power), B8 DC1VDD (power), B9 SCLK1, B10 ~{RESET} (out), B11 DBVDD1, C1 DNC, D1 DNC, D2 SDOUT1, D3 GPIO1 (io), E1 CIFMODE, F1 DBVDD2, F2 GPIO2 (io), F3 GPIO3 (io), G1 TEST, H1 CLKOUT, H2 GPIO7 (io), H3 GPIO8 (io), J1 DC3FB (in), K1 DC3VDD (power), K2 LDO13VOUT2 (power), K3 GPIO9 (io), L1 DC3LX (power), M1 DC3GND (power), M2 LDO9_10VDD (power), M3 LDO9VOUT (power), N1 DC4GND (power), N2 LDO7VOUT (power), N3 LDO10VOUT (power), P1 DC4LX (power), R1 DC4VDD (power), R2 LDO8VOUT (power), R3 LDO7_8VDD (power), T1 DC4FB (in), U1 PVDD1, U2 LED2 (in), U3 LED1 (in), V1 LDO6VOUT (power), V2 DNC, V3 LDO11VOUT (power), V4 PVDD3, W1 LDO6VDD (power), W2 LDO5VOUT (power), W3 LDO4VDD (power), W4 GPIO4 (io), W5 GPIO6 (io), W6 GPIO12 (io), W7 LDO13VOUT1 (power), W8 VREFC, W9 ~{ON} (in), W10 SDA2 (io), W11 XOSCGND, W12 BACKUPVDD, Y1 LDO5VDD (power), Y2 LDO4VOUT (power), Y3 PROGVDD, Y4 GPIO5 (io), Y5 GPIO10 (io), Y6 GPIO11 (io), Y7 PVDD2, Y8 LDO12VOUT (power), Y9 IREFR, Y10 SCLK2 (io), Y11 XTI, Y12 XTO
